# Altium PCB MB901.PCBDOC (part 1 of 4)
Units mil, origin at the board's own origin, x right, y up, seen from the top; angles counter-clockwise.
Board outline 4505 x 7005 mil, 4 copper layers (TopLayer, GND, VCC, BottomLayer); 333 components, 312 nets, 1570 pads, 794 vias.
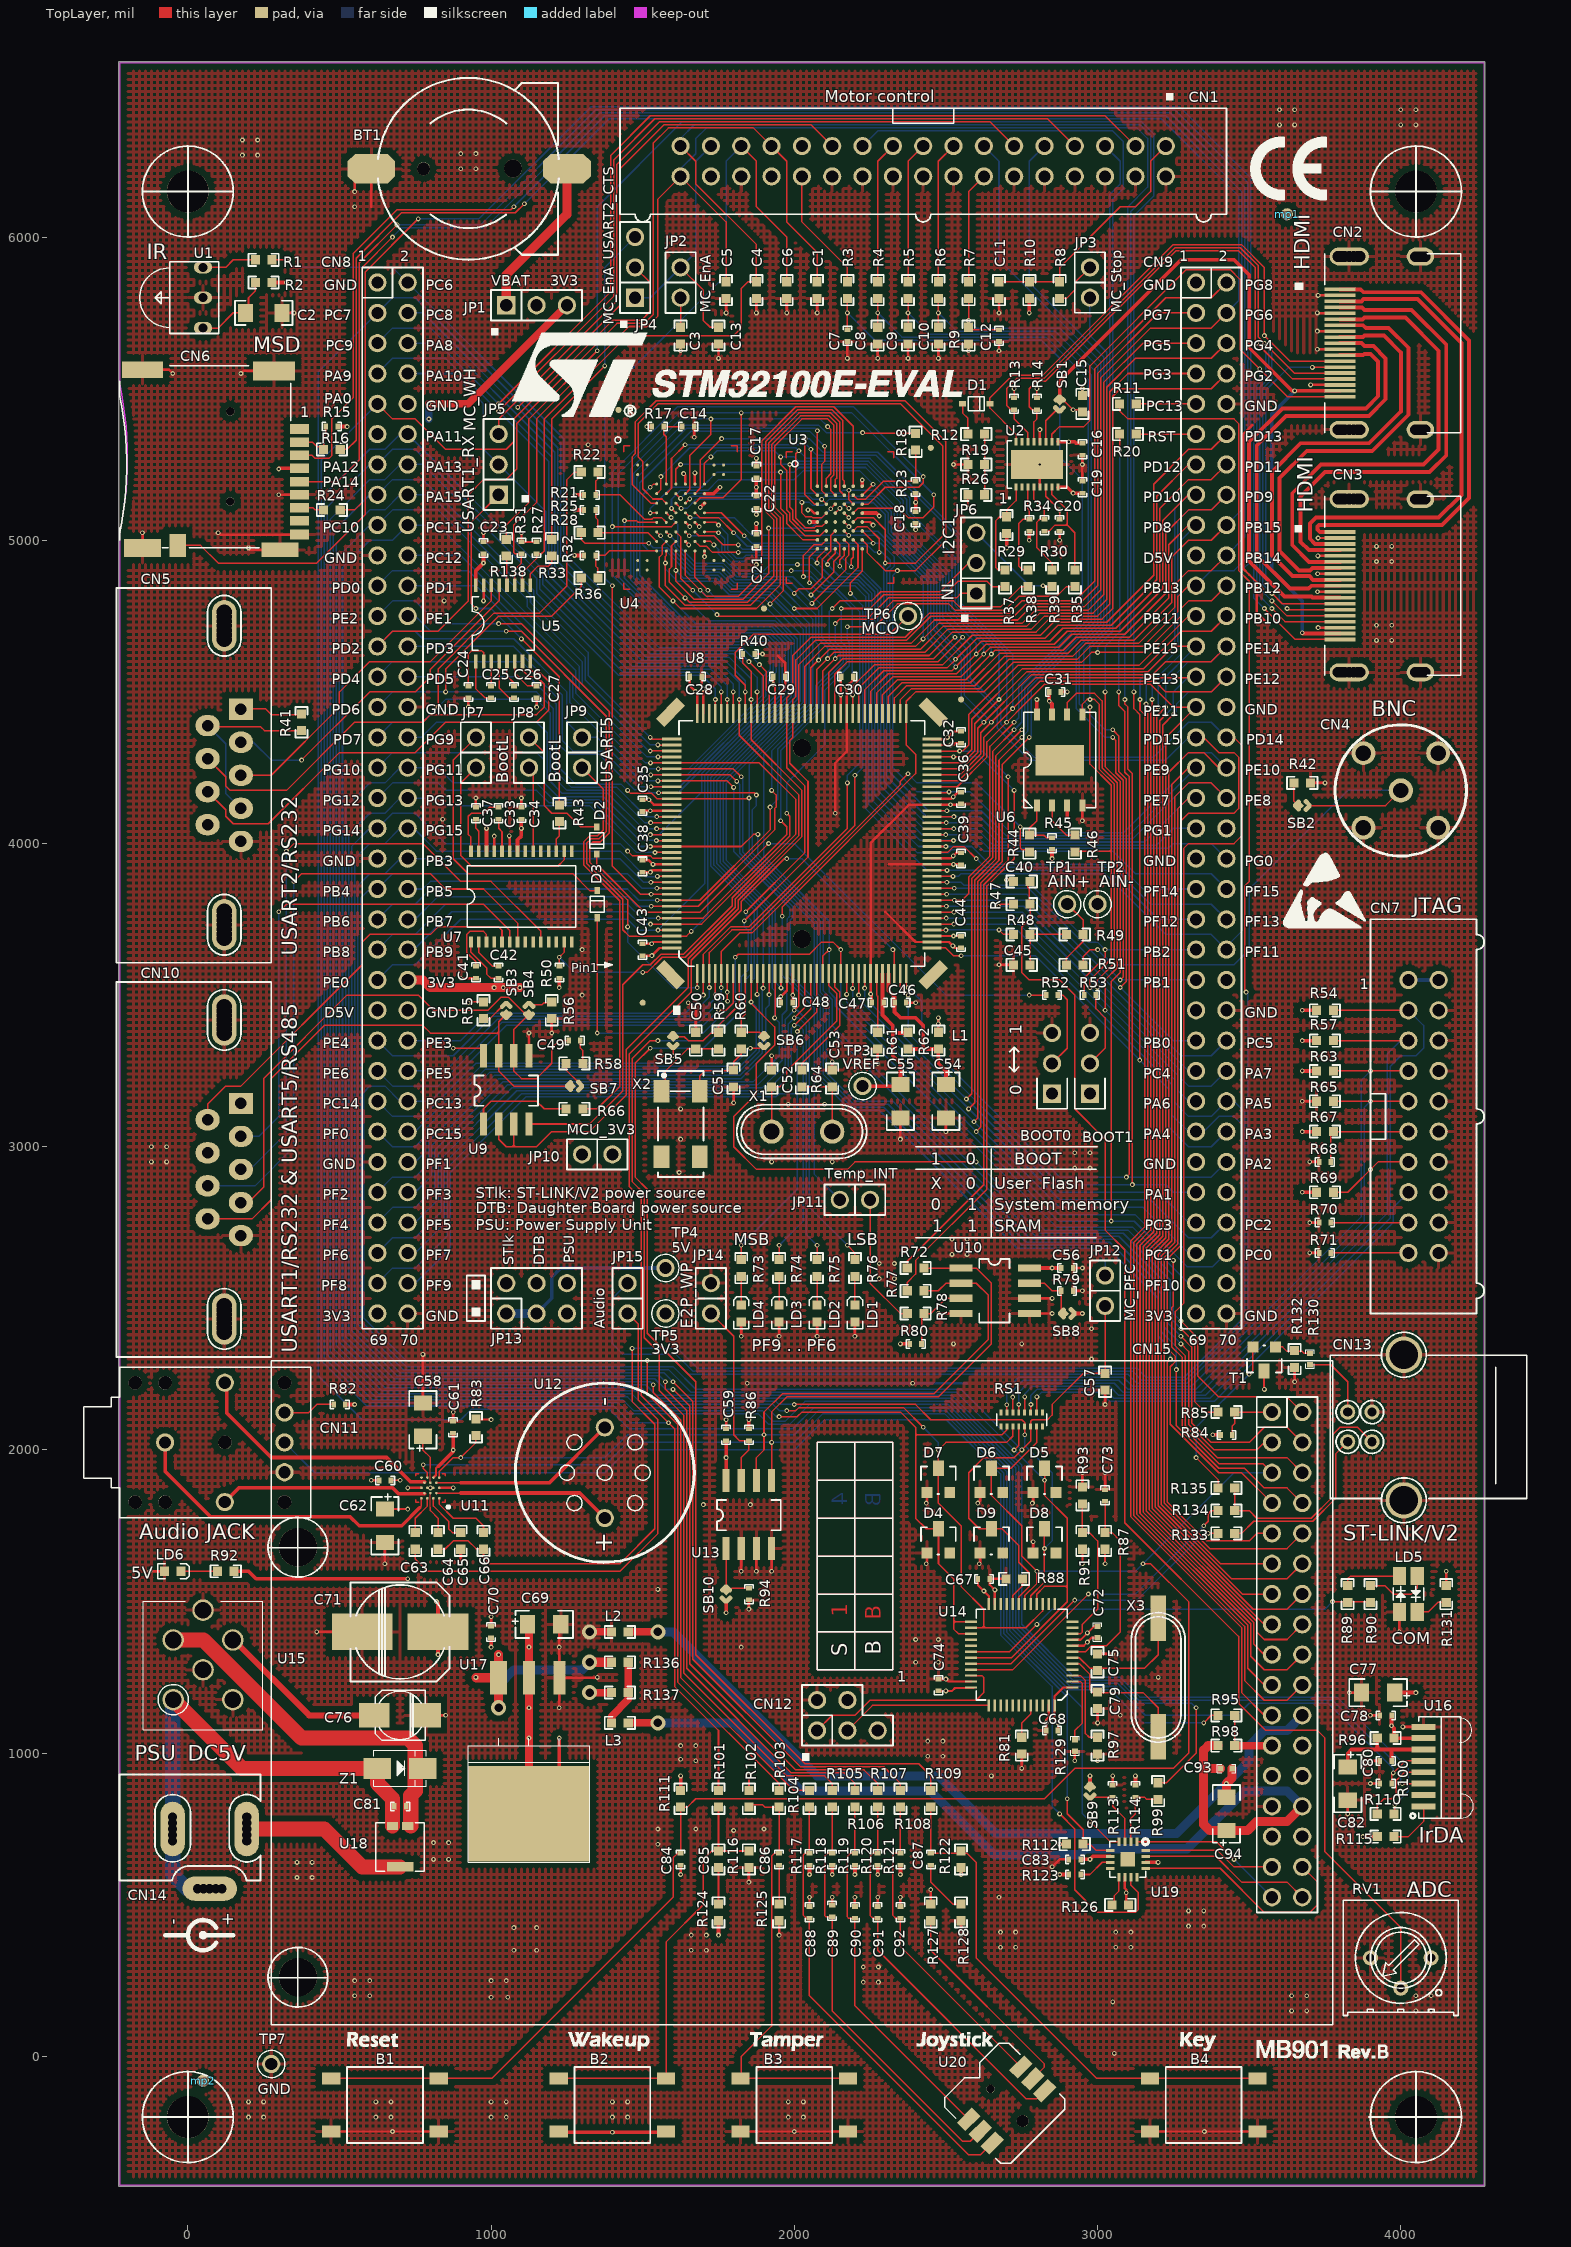
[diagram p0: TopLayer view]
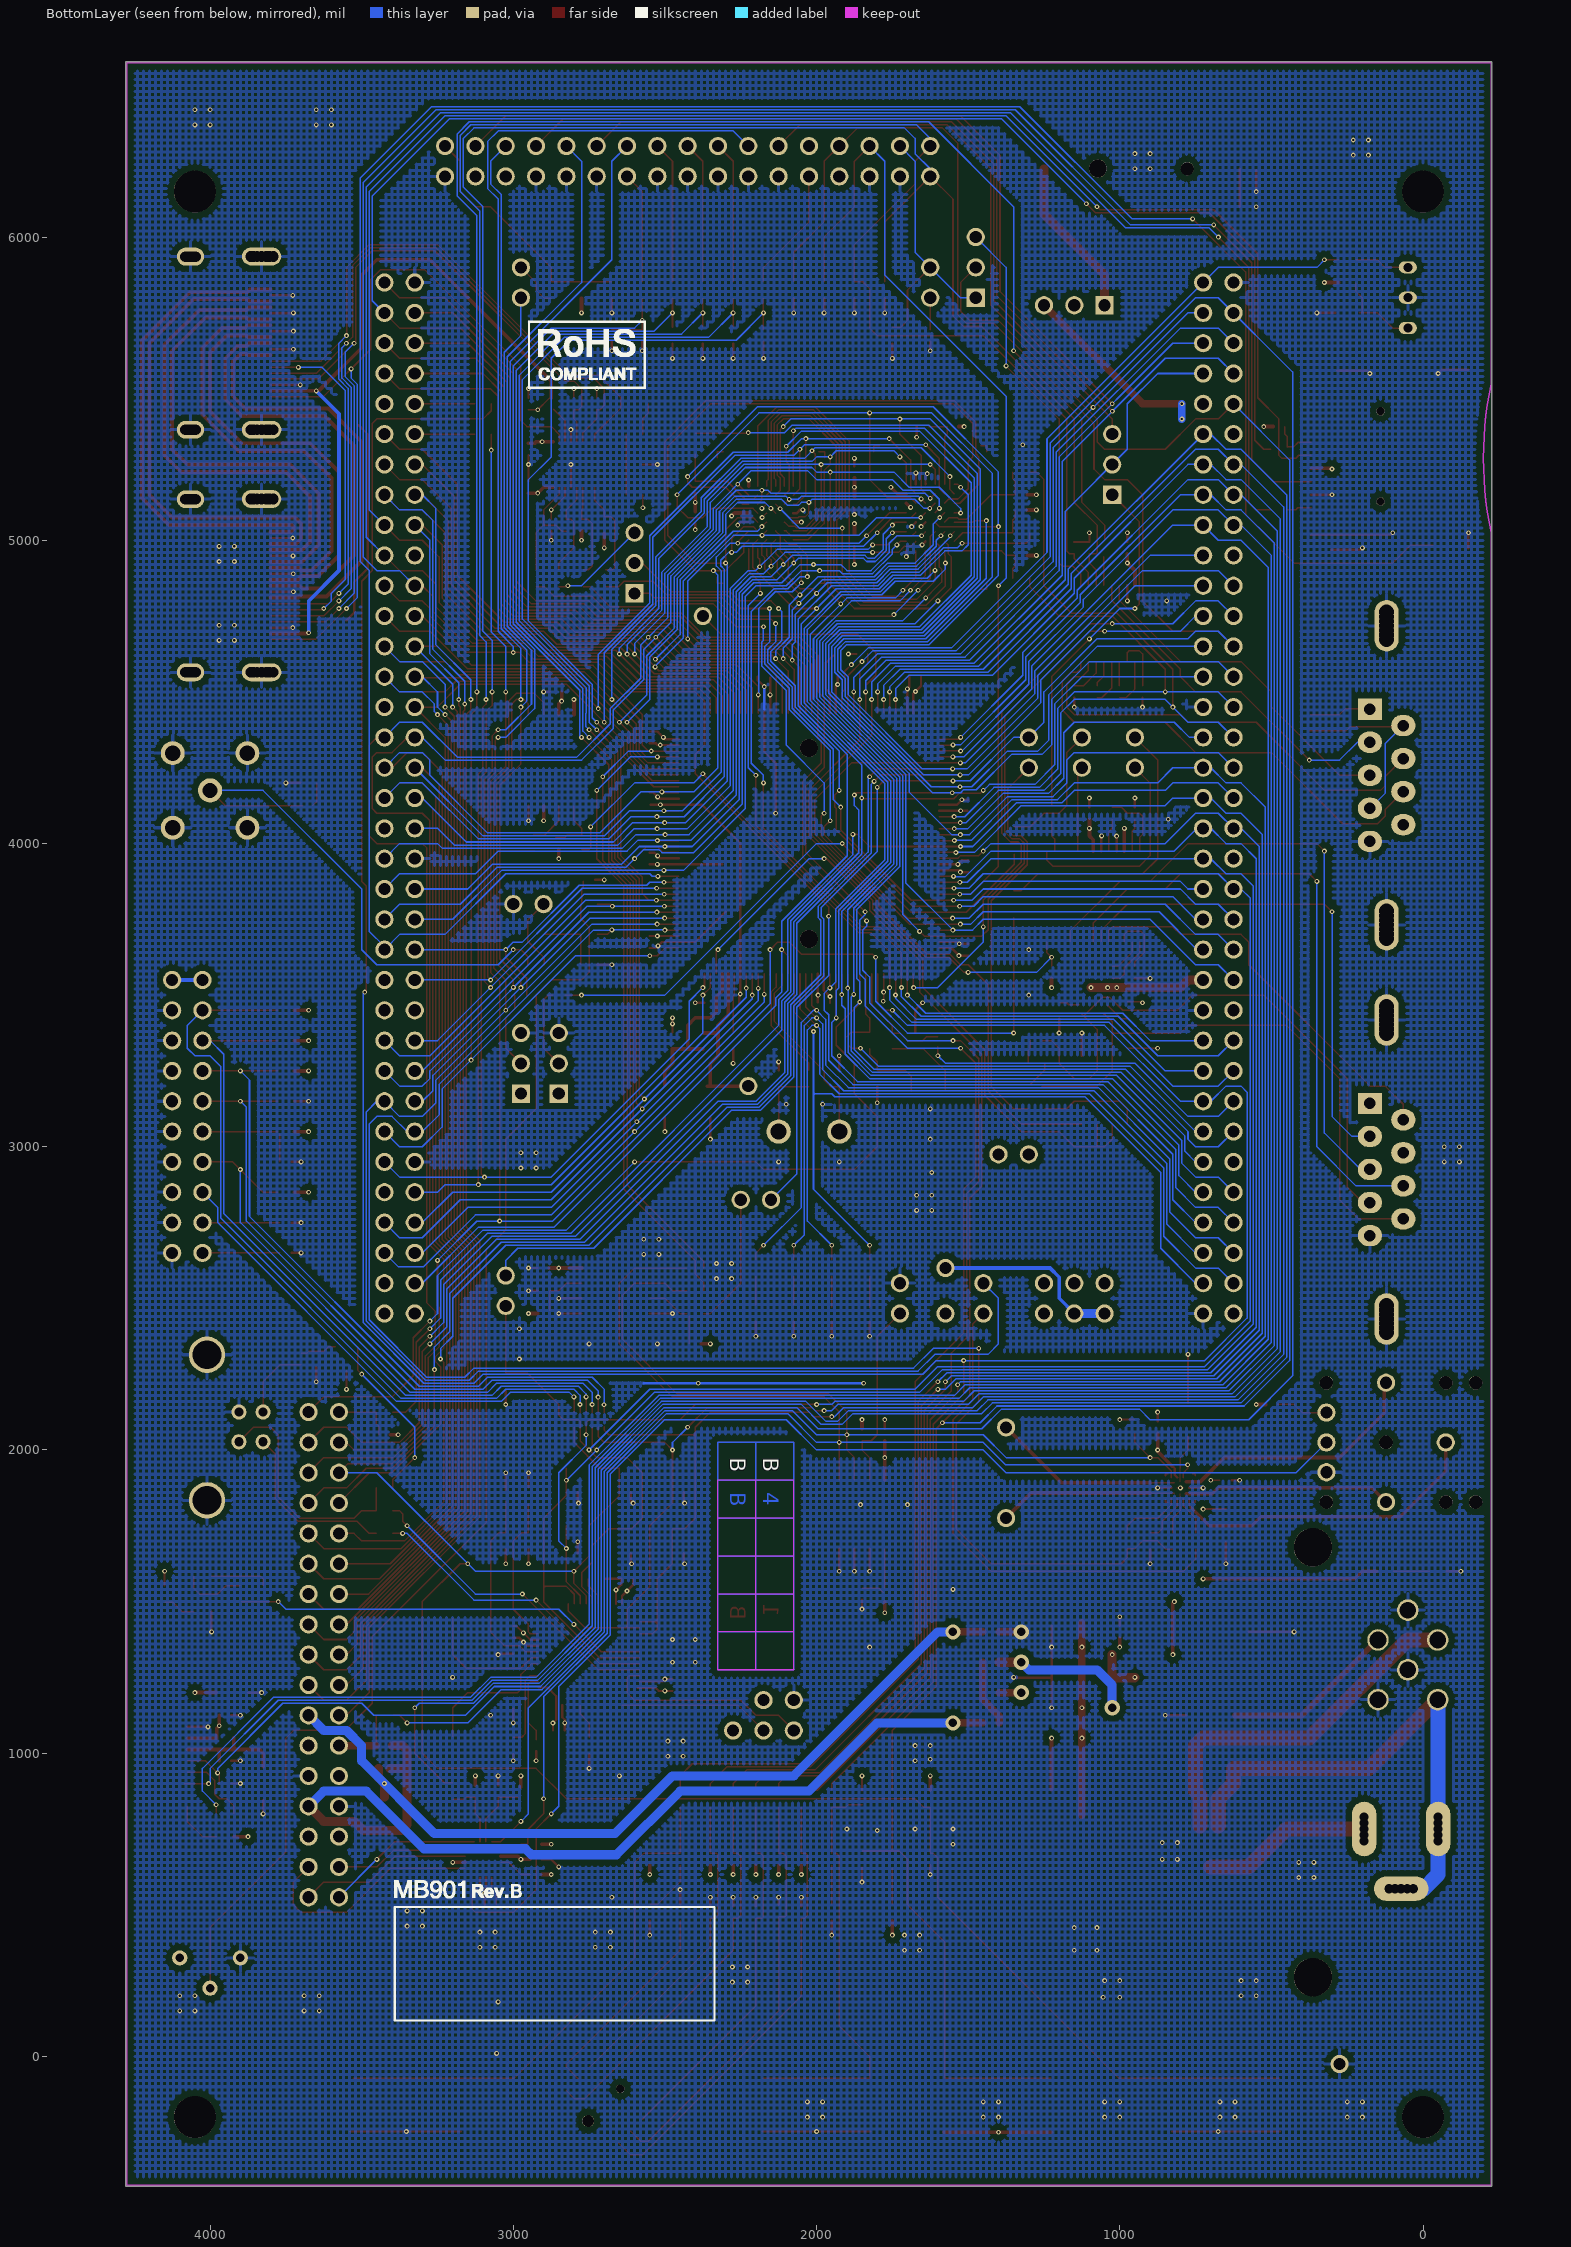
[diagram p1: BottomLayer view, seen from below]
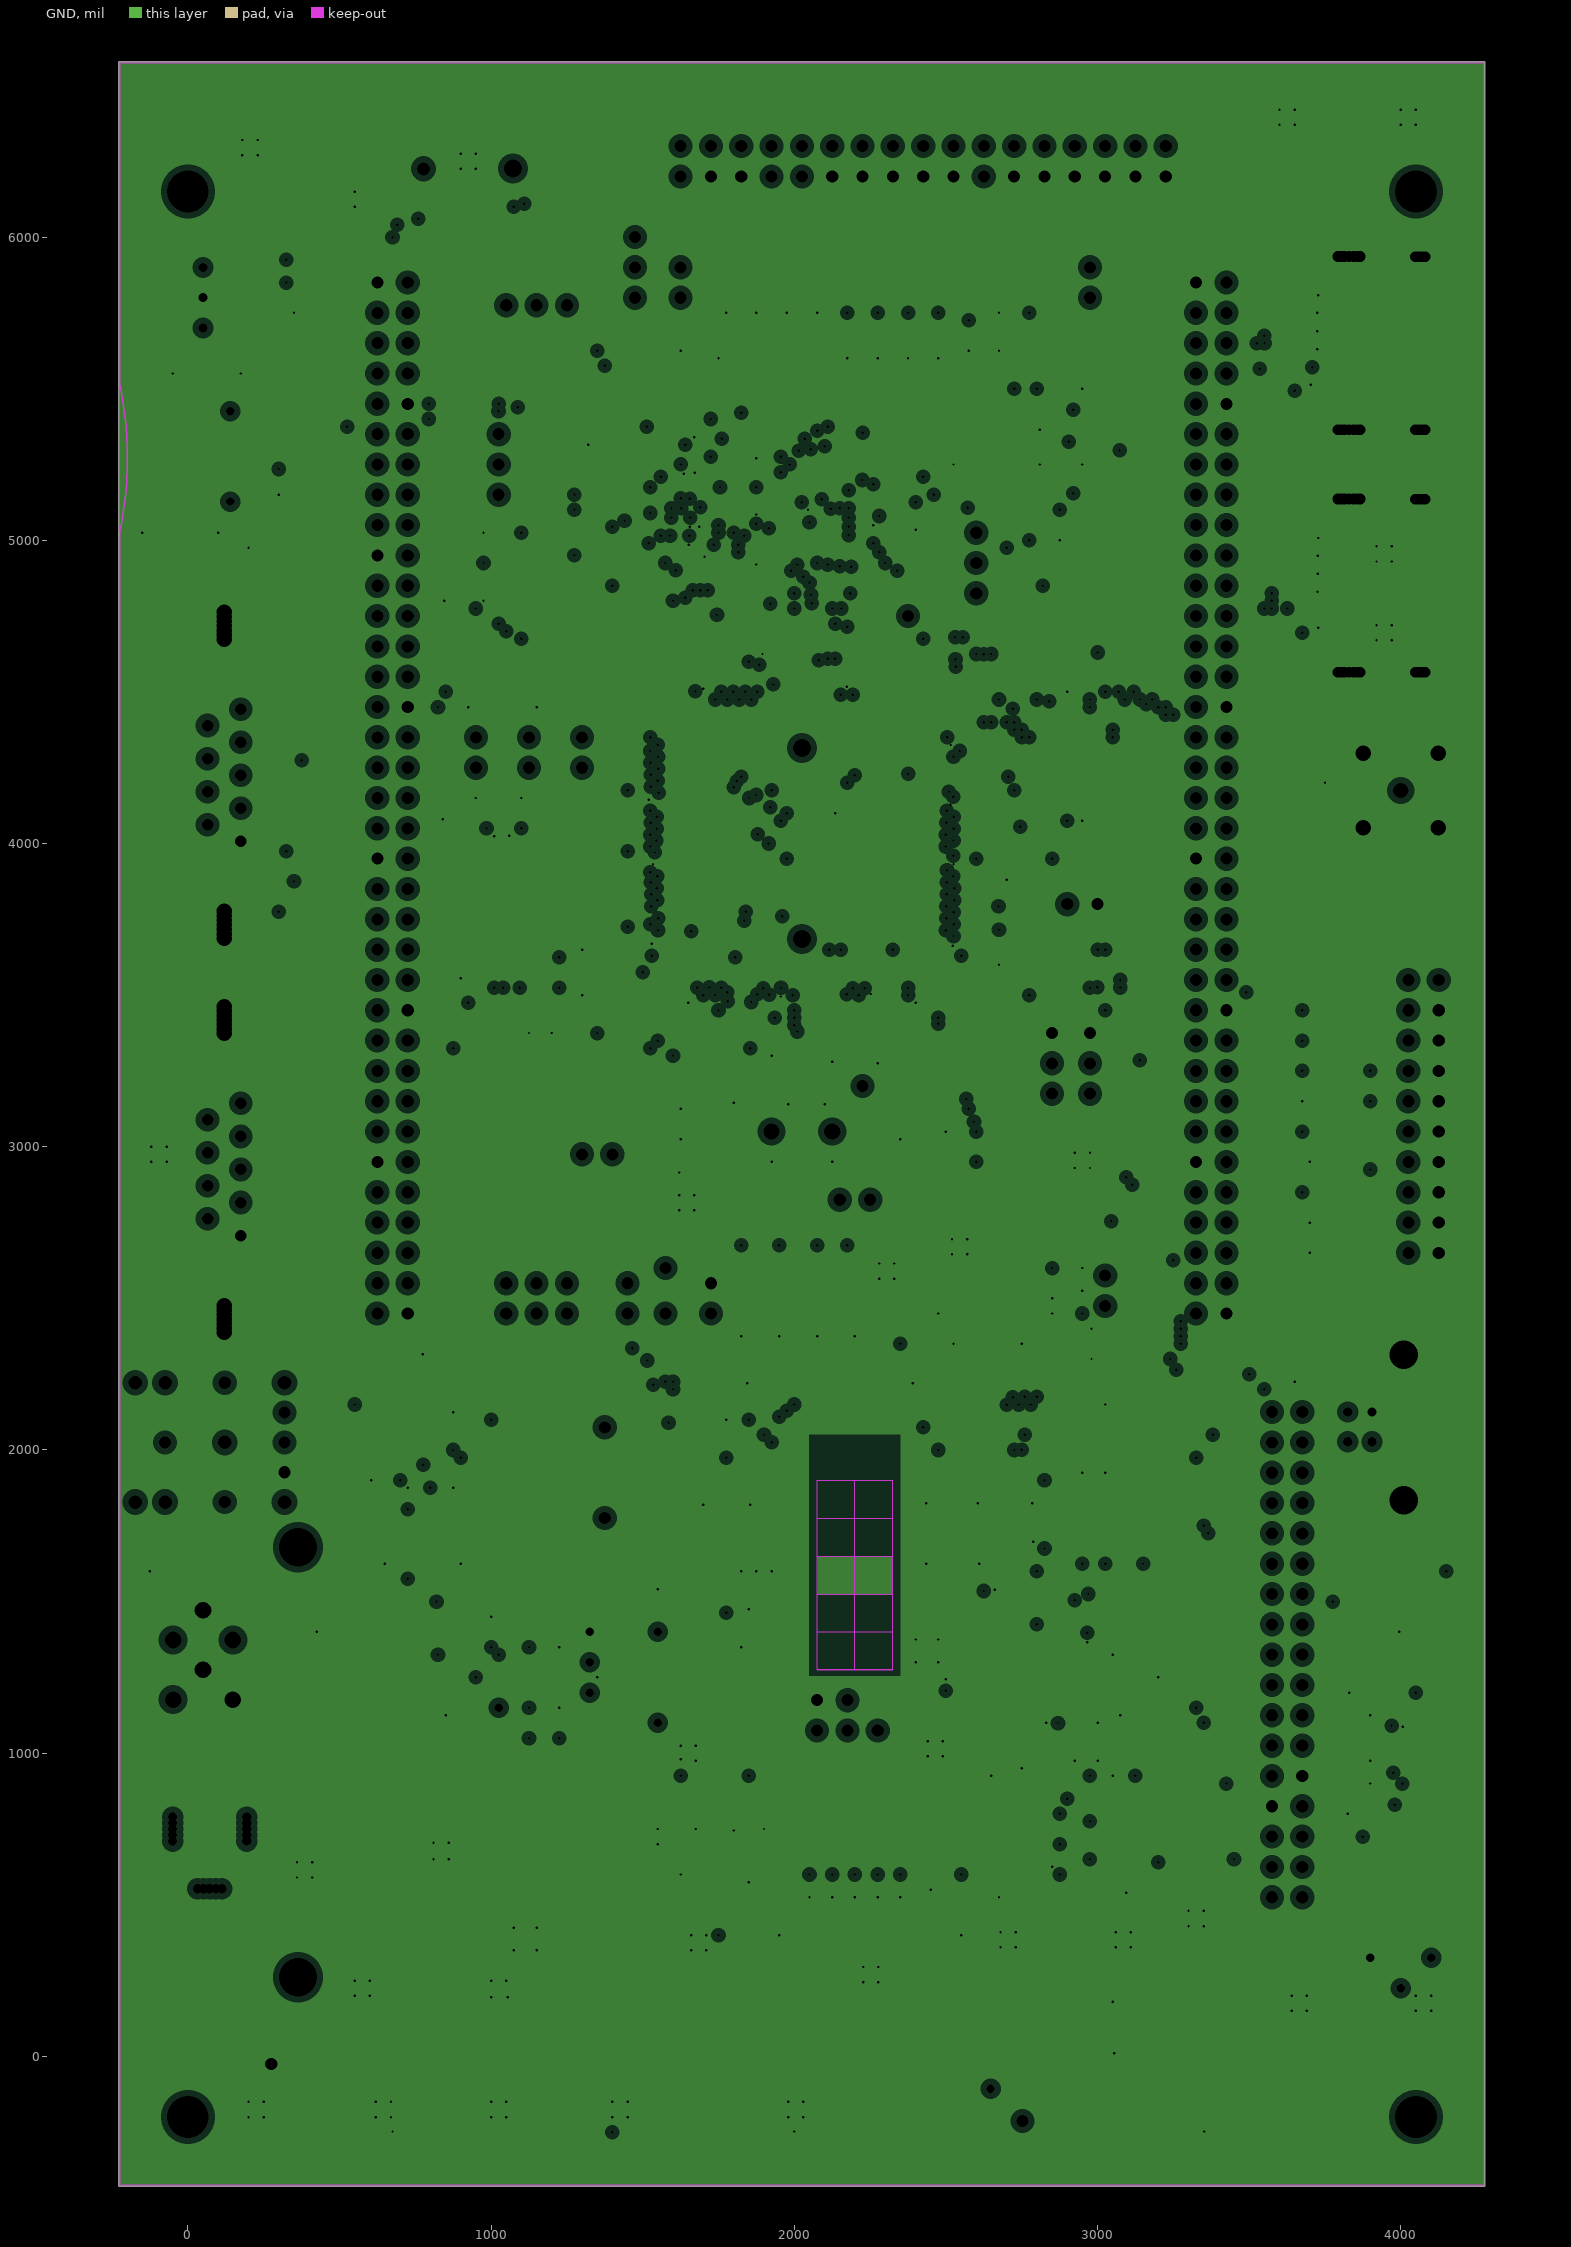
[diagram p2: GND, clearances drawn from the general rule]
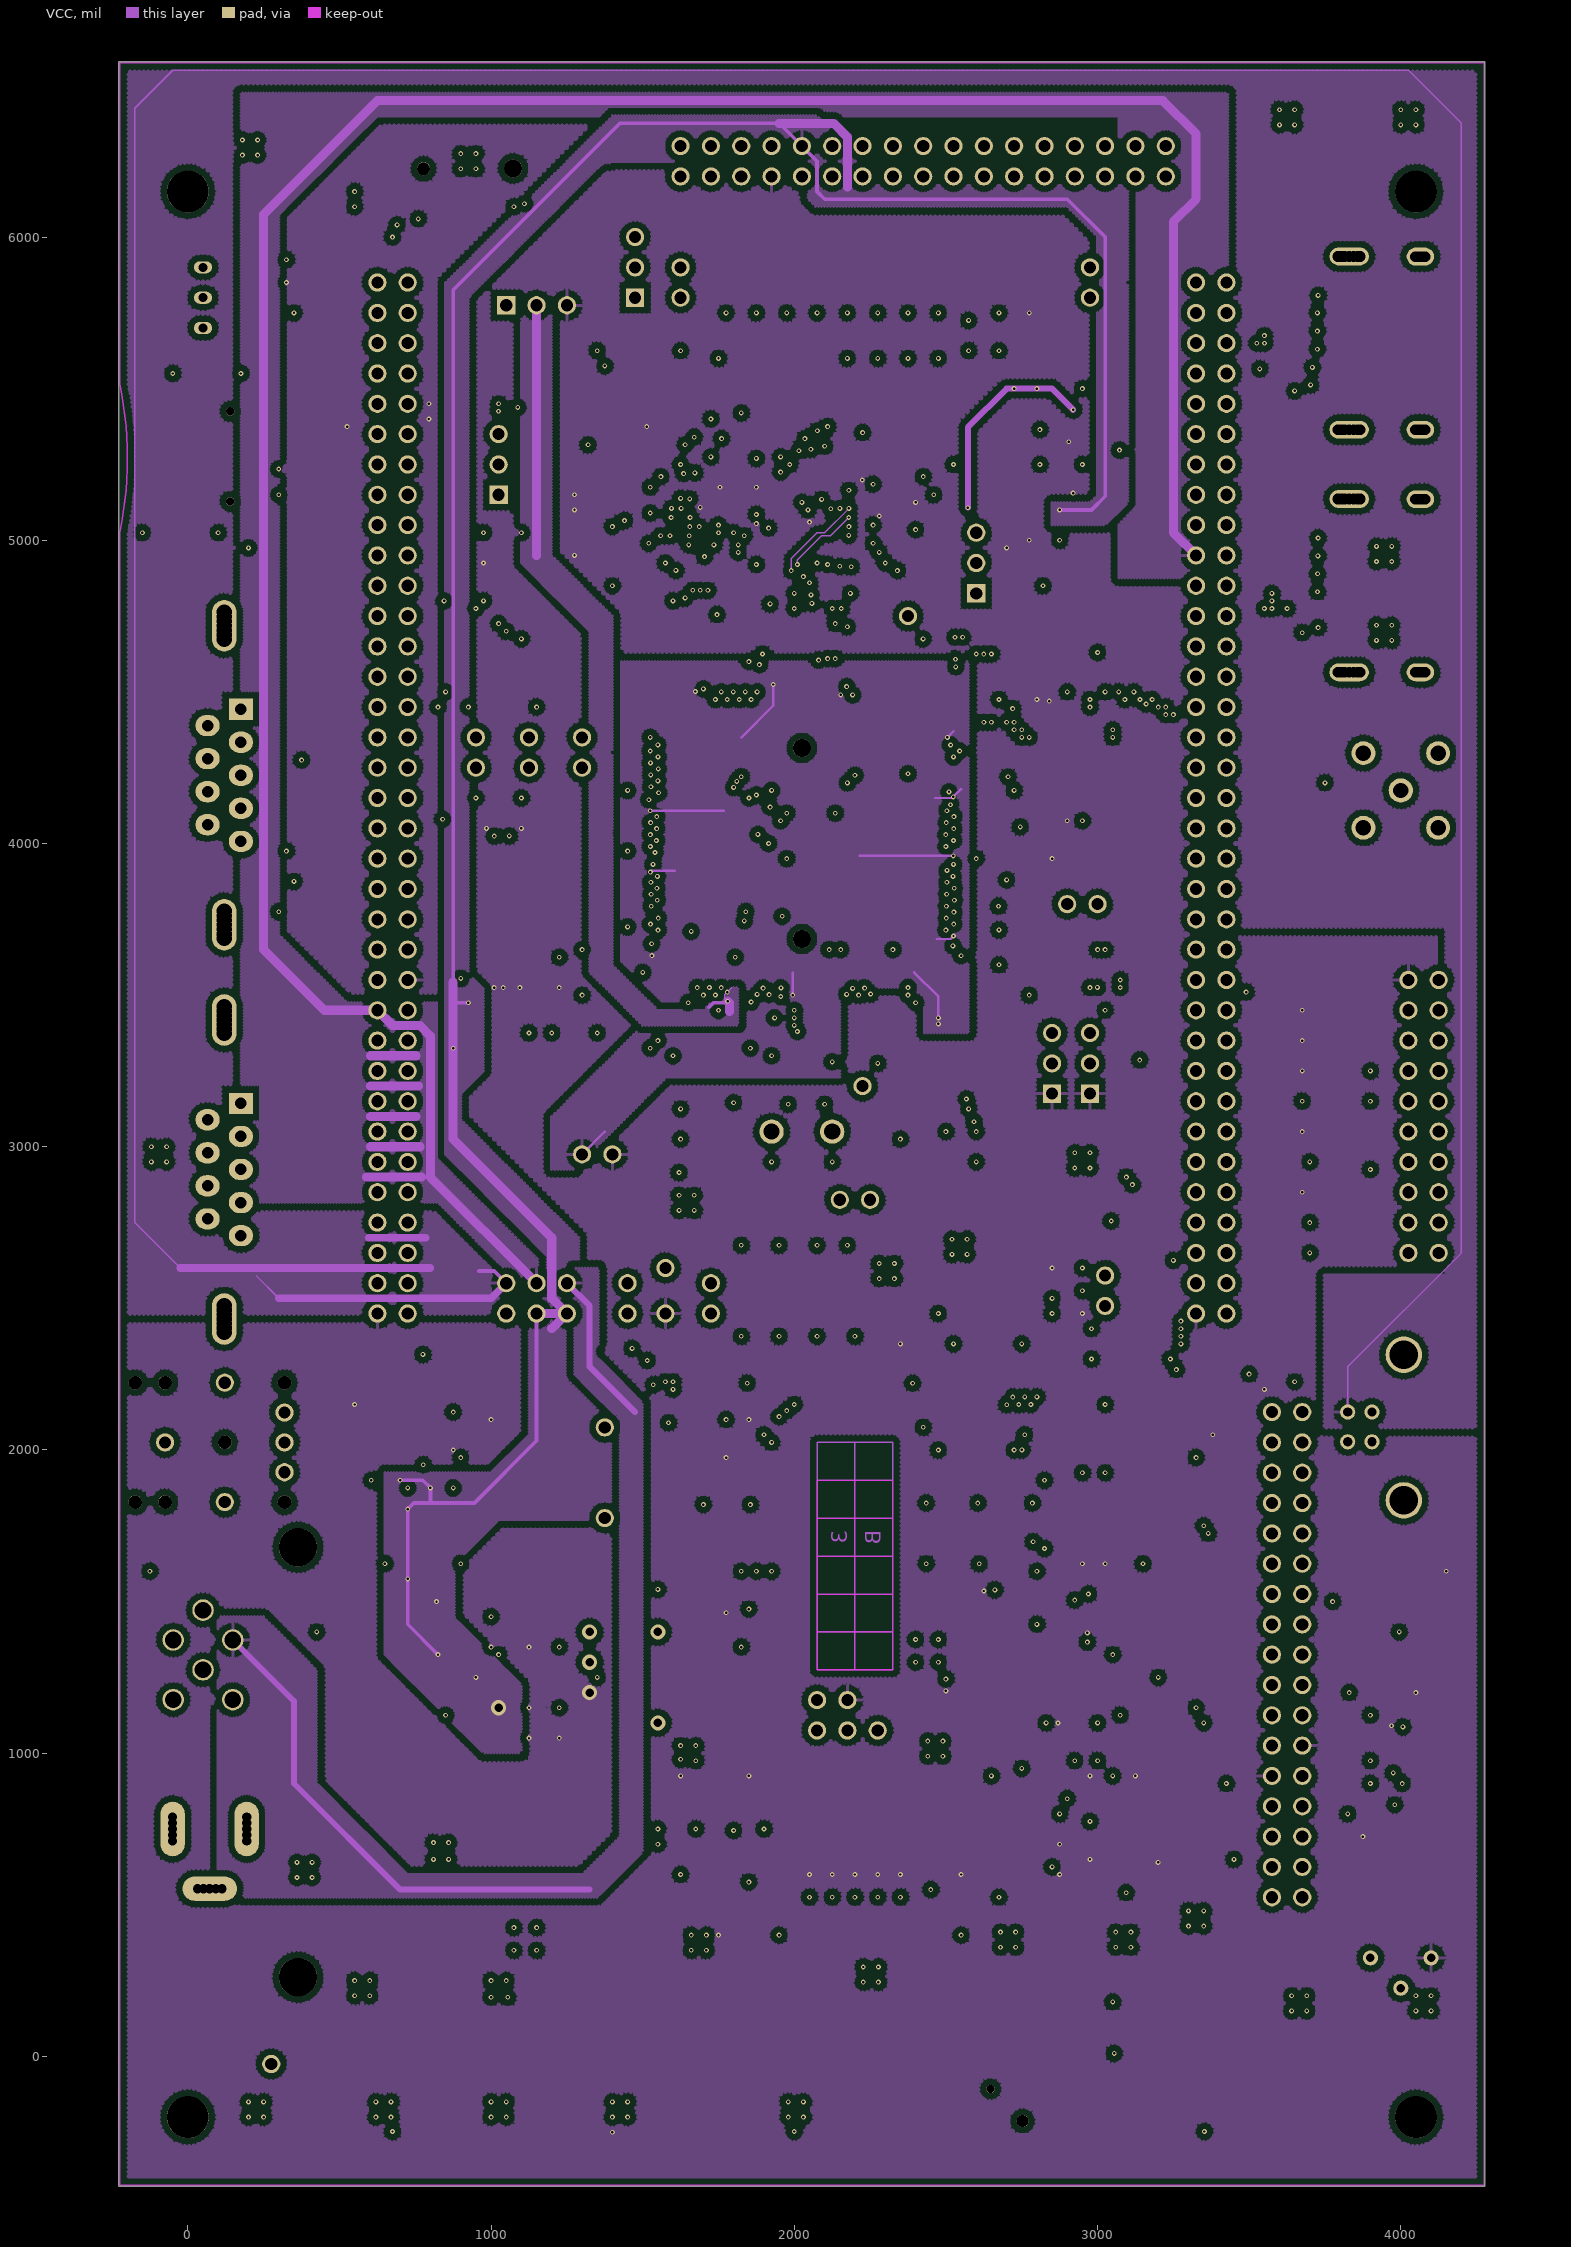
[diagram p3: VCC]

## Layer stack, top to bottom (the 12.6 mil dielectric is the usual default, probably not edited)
TopLayer: signal copper 1.4
Dielectric: core 12.6, FR-4, Dk 4.8
GND: plane copper 1.4, net GND
Dielectric: prepreg 12.6, FR-4, Dk 4.8
VCC: signal copper 1.4
Dielectric: core 12.6, FR-4, Dk 4.8
BottomLayer: signal copper 1.4

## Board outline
-227.5,-427.5 4277.5,-427.5 4277.5,6577.5 -227.5,6577.5

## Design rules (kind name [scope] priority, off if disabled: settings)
Clearance Clearance_3 [InComponent('U11')] p1: gap=4
Clearance Clearance_1 [(InPoly)] p2: gap=20 // Protel DXP Scope 1 Expression Was: (InPoly)   Protel DXP Scope 1 Expression Was: (InPoly)
Clearance [All] p3: gap=5
ComponentClearance [All] p1 off: gap=10 collisioncheckmode=0
PlaneClearance [All] p1: clearance=20
PlaneConnect [All] p1: planeconnectstyle=Relief reliefexpansion=20 reliefentries=4 reliefconductorwidth=10 reliefairgap=10
PolygonConnect [All] p1: connectstyle=Relief reliefconductorwidth=10 reliefentries=4 polygonreliefangle="90 Angle"
RoutingLayers [All] p1: top layer=Horizontal mid layer 1="Not Used" bottom layer=Vertical
RoutingVias [All] p1: holewidth=8 width=16 viastyle="Through Hole" minholewidth=5 minwidth=8 maxholewidth=28 maxwidth=50
SolderMaskExpansion [All] p1: expansion=4
TestPointUsage [All] p1: valid=0 allowmultiple=FALSE
Testpoint [All] p1: side=15 testpointundercomponent=TRUE minsize=40 maxsize=100 preferedsize=60 minholesize=20 maxholesize=40 preferedholesize=32 testpointgrid=1 style=1023 order=1234567890
Width Width_4 [InNet('E5V')] p1: maxlimit=300 minlimit=7 preferedwidth=20
Width Width_3 [InNet('D5V')] p2: maxlimit=300 minlimit=7 preferedwidth=30
Width Width_1 [InNet('+3V3')] p3: maxlimit=300 minlimit=7 preferedwidth=12
Width Width_5 [InNet('GND')] p4: maxlimit=300 minlimit=7 preferedwidth=8
Width Width_8 [InNet('VDDA')] p5: maxlimit=300 minlimit=7 preferedwidth=12
Width Width_7 [InNet('VDD')] p6: maxlimit=300 minlimit=7 preferedwidth=8
Width Width_6 [InNet('U5V')] p7: maxlimit=300 minlimit=7 preferedwidth=12
Width Width_2 [InNet('+5V')] p8: maxlimit=300 minlimit=5 preferedwidth=12
Width [All] p9: maxlimit=300 minlimit=5 preferedwidth=5
14 further rules are at their usual default settings.

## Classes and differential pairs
net class A[0..20]: A0 A1 A2 A3 A4 A5 A6 A7 A8 A9 A10 A11 A12 A13 A14 A15 A16 A17 A18 A19 A20 A[0..20]0 A[0..20]1 A[0..20]2 A[0..20]3 A[0..20]4 A[0..20]5 A[0..20]6 A[0..20]7 A[0..20]8 A[0..20]9 A[0..20]10 A[0..20]11 A[0..20]12 A[0..20]13 A[0..20]14 A[0..20]15 A[0..20]16 A[0..20]17 A[0..20]18 A[0..20]19 A[0..20]20
component class MB901: R72 R77 R83 R112
component class SRAM&OneNAND: C14 C17 C18 C21 C22 R17 R18 R21 R22 R23 R25 R28 R32 R36 U3 U4
component class MicroSD&SPIFlash: C31 CN6 R15 R16 R24 R44 R45 R46 U6
component class LCD&EEPROM&TS: C56 C59 C83 CN15 JP14 R78 R79 R80 R84 R85 R86 R94 R95 R98 R99 R113 R114 R123 R126 SB8 SB9 SB10 U10 U13 U19
component class ST_LINK: C67 C68 C72 C73 C74 C75 C79 CN12 CN13 LD5 R81 R87 R88 R89 R90 R91 R93 R97 U14 X3
component class CEC&IRreceiver: C2 C15 C16 C19 C20 CN2 CN3 D1 R1 R2 R12 R13 R14 R19 R26 R29 R30 R34 R35 R37 R38 R39 SB1 U1 U2
component class IO_Peripheral: B2 B3 B4 C40 C45 C85 C86 C87 C88 C89 C90 C91 C92 CN4 LD3 LD4 R42 R47 R48 R49 R51 R73 R74 R75 R76 R101 R102 R103 R104 R105 R106 R107 R108 R109 R116 R117 R118 R119 R120 R121 R122 R124 R125 R127 R128 RV1 SB2 TP1 TP2 U20
net class A[0..23]: A0 A1 A2 A3 A4 A5 A6 A7 A8 A9 A10 A11 A12 A13 A14 A15 A16 A17 A18 A19 A20 A21 A22 A23 A[0..23]0 A[0..23]1 A[0..23]2 A[0..23]3 A[0..23]4 A[0..23]5 A[0..23]6 A[0..23]7 A[0..23]8 A[0..23]9 A[0..23]10 A[0..23]11 A[0..23]12 A[0..23]13 A[0..23]14 A[0..23]15 A[0..23]16 A[0..23]17 A[0..23]18 A[0..23]19 A[0..23]20 A[0..23]21 A[0..23]22 A[0..23]23
net class D[0..15]: D0 D1 D2 D3 D4 D5 D6 D7 D8 D9 D10 D11 D12 D13 D14 D15 D[0..15]0 D[0..15]1 D[0..15]2 D[0..15]3 D[0..15]4 D[0..15]5 D[0..15]6 D[0..15]7 D[0..15]8 D[0..15]9 D[0..15]10 D[0..15]11 D[0..15]12 D[0..15]13 D[0..15]14 D[0..15]15
net class A[0..25]: A0 A1 A2 A3 A4 A5 A6 A7 A8 A9 A10 A11 A12 A13 A14 A15 A16 A17 A18 A21 A22 A[0..25]0 A[0..25]1 A[0..25]2 A[0..25]3 A[0..25]4 A[0..25]5 A[0..25]6 A[0..25]7 A[0..25]8 A[0..25]9 A[0..25]10 A[0..25]11 A[0..25]12 A[0..25]13 A[0..25]14 A[0..25]15 A[0..25]16 A[0..25]17 A[0..25]18 A[0..25]19 A[0..25]20 A[0..25]21 A[0..25]22 A[0..25]23 A[0..25]24 A[0..25]25 D0 D1 PD3 PG13 PG14
component class MotorCtrl_2: C28 C29 C30 C32 C35 C36 C39 C43 C44 C48 CN8 JP26 R36 R49 R51 R61 R62 R72 R96 R113
component class SRAM&Flash: C24 C25 C27 C40 C50 C53 C73 C84 JP2 JP5 JP7 JP9 R2 R12 R26 R28 R31 R35 R68 U11 U12
component class CFcard: C27 C50 C53 CN4 R12 R25 R28 R31 R35 R44 R46 R52 R67 R71 U11
net class PE[0..15]: A19 A20 A21 A22 A23 NetR41_2 NetR115_2 PE7 PE8 PE9 PE10 PE11 PE12 PE13 PE14 PE15 PE[0..15]0 PE[0..15]1 PE[0..15]2 PE[0..15]3 PE[0..15]4 PE[0..15]5 PE[0..15]6 PE[0..15]7 PE[0..15]8 PE[0..15]9 PE[0..15]10 PE[0..15]11 PE[0..15]12 PE[0..15]13 PE[0..15]14 PE[0..15]15
net class PD[0..15]: NetR72_2 NetR96_2 NetU14_4 NetU14_5 PB14 PD0 PD1 PD2 PD3 PD4 PD5 PD6 PD10 PD11 PD13 PD[0..15]0 PD[0..15]1 PD[0..15]2 PD[0..15]3 PD[0..15]4 PD[0..15]5 PD[0..15]6 PD[0..15]7 PD[0..15]8 PD[0..15]9 PD[0..15]10 PD[0..15]11 PD[0..15]12 PD[0..15]13 PD[0..15]14 PD[0..15]15 PG7
net class PC[0..15]: NetC50_1 PC0 PC1 PC2 PC3 PC4 PC5 PC6 PC7 PC8 PC9 PC10 PC11 PC12 PC13 PC15 PC[0..15]0 PC[0..15]1 PC[0..15]2 PC[0..15]3 PC[0..15]4 PC[0..15]5 PC[0..15]6 PC[0..15]7 PC[0..15]8 PC[0..15]9 PC[0..15]10 PC[0..15]11 PC[0..15]12 PC[0..15]13 PC[0..15]14 PC[0..15]15
net class PB[0..15]: NetR78_1 NetU15_5 PB0 PB1 PB2 PB3 PB4 PB8 PB10 PB11 PB12 PB13 PB14 PB[0..15]0 PB[0..15]1 PB[0..15]2 PB[0..15]3 PB[0..15]4 PB[0..15]5 PB[0..15]6 PB[0..15]7 PB[0..15]8 PB[0..15]9 PB[0..15]10 PB[0..15]11 PB[0..15]12 PB[0..15]13 PB[0..15]14 PB[0..15]15 PG8 TEMPERATURESENSOR_SCL TEMPERATURESENSOR_SDA
net class PA[0..15]: PA0 PA1 PA2 PA3 PA4 PA5 PA6 PA7 PA8 PA9 PA10 PA11 PA12 PA13 PA14 PA15 PA[0..15]0 PA[0..15]1 PA[0..15]2 PA[0..15]3 PA[0..15]4 PA[0..15]5 PA[0..15]6 PA[0..15]7 PA[0..15]8 PA[0..15]9 PA[0..15]10 PA[0..15]11 PA[0..15]12 PA[0..15]13 PA[0..15]14 PA[0..15]15
component class Extension: CN1 CN14 R103 R109
component class JTAG&SWD: CN1 CN5 CN18 JP19 R4 R5 R6 R7 R8 R9 R10 R27 R31 R55 R64 R92 R100
component class MotorCtrl: C1 C6 C23 C24 C33 C57 C71 C86 C87 C90 C91 C92 CN5 JP5 JP12 R14 R61 R76 R82 R88 R91 R105 R107
component class MCU: B1 BOOT0 BOOT1 BT1 C4 C5 C6 C8 C9 C13 C23 C37 C57 C67 C75 C77 JP7 L1 R12 R48 R90 R119 R120 R121 R125 R128 TP10 U8 X1 X2
component class Peripherals: C7 C31 C39 C68 C79 CN3 CN4 CN9 JP8 JP9 JP14 LD3 LD4 LD6 R3 R11 R14 R19 R25 R27 R30 R44 R46 R47 R52 R56 R61 R63 R67 R69 R71 R75 R76 R82 R83 R101 R102 R103 R105 R107 R109 R110 R111 R125 RV1 T1 T2 TR1 TR2 U2 U4 U6 U15
component class Power: C69 C70 C71 C76 C81 CN14 JP13 LD4 R92 TP4 TP5 TP7 U15 U17 U18 Z1
component class RS232&IrDA: C23 C24 C25 C26 C27 C32 C38 C47 C48 C77 C78 C80 C81 C82 CN5 CN10 JP15 R33 R41 R50 R57 R83 R96 R100 R110 R115 U5 U16 U18
component class Audio: C25 C27 C40 C50 C53 C73 C84 C85 CN7 JP11 JP16 R2 R12 R25 R26 R28 R35 R44 R46 R52 R55 R67 R68 R71 R105 RV2 RV3 TP4 TP5 TP7 TP15 U15 U18 U19 U20
component class LCD&Joystick: B1 B2 B4 C33 C85 C86 C87 C88 C89 C90 C91 C92 R5 R10 R58 R87 R101 R102 R103 R104 R105 R106 R107 R108 R109 R115 R116 R117 R118 R119 R120 R121 R122 R124 R125 R127 R128 U18 U19 U20
component class MC&Extension: C1 C6 C23 C24 C33 C71 C86 C87 C90 C91 C92 CN1 CN5 CN14 JP12 R14 R61 R76 R82 R88 R91 R103 R105 R109
component class SD&SmartCard: C1 C6 C57 C69 C76 C81 CN1 CN10 R4 R31 R41 R50 R96 R100 R101 R115 R116 R117 R119 TP8 TP9 U15
component class Debug: CN1 CN5 CN9 CN18 JP19 R4 R5 R8 R9 R10 R27 R64 R92

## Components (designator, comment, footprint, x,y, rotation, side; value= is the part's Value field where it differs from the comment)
B1 "RESET" PB10 650,-160 r90 top
B2 "WKUP" PB10 1400,-160 r90 top
B3 "Tamper" PB10 2000,-160 r90 top
B4 "USER" PB10 3350,-160 r90 top
BOOT0 "" SIP3 2850,3175 r90 top
BOOT1 "" SIP3 2975,3175 r90 top
BT1 "CR1220 holder" LI1220_1 925,6225 r0 top
C1 "[N/A]" 0603C 2075,5825 r270 top
C2 "4.7uF" 1206C 250,5750 r180 top
C3 "10nF" 0603C 1625,5675 r270 top
C4 "[N/A]" 0603C 1875,5825 r270 top
C5 "[N/A]" 0603C 1775,5825 r270 top
C6 "[N/A]" 0603C 1975,5825 r270 top
C7 "100nF" 0402C#1 2175,5675 r270 top
C8 "[N/A]" 0603C 2275,5675 r270 top
C9 "[N/A]" 0603C 2375,5675 r270 top
C10 "[N/A]" 0603C 2475,5675 r270 top
C11 "1nF" 0603C 2675,5825 r270 top
C12 "100nF" 0402C#1 2675,5675 r270 top
C13 "[N/A]" 0603C 1750,5675 r270 top
C14 "100nF" 0402C#1 1650,5375 r0 top
C15 "10nF" 0603C 2950,5450 r270 top
C16 "100nF" 0402C#1 2950,5300 r90 top
C17 "100nF" 0402C#1 1875,5225 r90 top
C18 "100nF" 0402C#1 2400,5075 r90 top
C19 "100nF" 0402C#1 2950,5175 r270 top
C20 "100nF" 0402C#1 2875,5050 r90 top
C21 "100nF" 0402C#1 1875,5000 r90 top
C22 "100nF" 0402C#1 1875,5125 r270 top
C23 "100nF" 0402C#1 975,4975 r270 top
C24 "100nF" 0402C#1 925,4500 r270 top
C25 "100nF" 0402C#1 1000,4500 r270 top
C26 "100nF" 0402C#1 1075,4500 r270 top
C27 "100nF" 0402C#1 1150,4500 r270 top
C28 "100nF" 0402C#1 1675,4550 r180 top
C29 "100nF" 0402C#1 1950,4550 r180 top
C30 "100nF" 0402C#1 2175,4550 r180 top
C31 "100nF" 0402C#1 2860,4500 r0 top
C32 "100nF" 0402C#1 2550,4350 r90 top
C33 "100nF" 0402C#1 1025,4100 r270 top
C34 "100nF" 0402C#1 1100,4100 r90 top
C35 "100nF" 0402C#1 1500,4125 r270 top
C36 "100nF" 0402C#1 2550,4150 r90 top
C37 "100nF" 0402C#1 950,4100 r270 top
C38 "100nF" 0402C#1 1500,3925 r270 top
C39 "100nF" 0402C#1 2550,3950 r90 top
C40 "10nF" 0603C 2750,3875 r180 top
C41 "100nF" 0402C#1 950,3575 r90 top
C42 "100nF" 0402C#1 1025,3575 r270 top
C43 "100nF" 0402C#1 1500,3650 r270 top
C44 "100nF" 0402C#1 2550,3675 r90 top
C45 "[N/A]" 0603C 2750,3600 r180 top
C46 "100nF" 0402C#1 2350,3475 r0 top
C47 "100nF" 0402C#1 2275,3475 r0 top
C48 "100nF" 0402C#1 1975,3475 r0 top
C49 "100nF" 0402C#1 1275,3350 r0 top
C50 "6.8pF" 0603C 1675,3350 r270 top
C51 "6.8pF" 0603C 1800,3225 r90 top
C52 "20pF" 0603C 1925,3225 r270 top
C53 "20pF" 0603C 2125,3225 r270 top
C54 "1uF" TAN-A#1 2500,3150 r270 top
C55 "1uF" TAN-A#1 2350,3150 r270 top
C56 "100nF" 0402C#1 2900,2600 r0 top
C57 "[N/A]" 0603C 3025,2225 r270 top
C58 "1uF" TAN-A#1 775,2100 r90 top
C59 "100nF" 0402C#1 1775,2050 r90 top
C60 "100nF" 0402C#1 650,1900 r0 top
C61 "100nF" 0402C#1 875,2075 r270 top
C62 "1uF" TAN-A#1 650,1750 r270 top
C63 "330nF" 0603C 750,1700 r90 top
C64 "330nF" 0603C 825,1700 r90 top
C65 "330nF" 0603C 900,1700 r90 top
C66 "330nF" 0603C 975,1700 r90 top
C67 "100nF" 0402C#1 2625,1575 r0 top
C68 "100nF" 0402C#1 2850,1075 r180 top
C69 "10uF" TAN-A#1 1175,1425 r0 top
C70 "100nF" 0402C#1 1000,1400 r270 top
C71 "220uF" C310M 700,1400 r0 top
C72 "100nF" 0402C#2 3000,1400 r270 top
C73 "100nF" 0402C#1 3025,1850 r90 top
C74 "100nF" 0402C#1 2475,1225 r270 top
C75 "20pF" 0603C 3000,1300 r90 top
C76 "10uF" C160M 700,1125 r180 top
C77 "4.7uF" TAN-A#1 3925,1200 r180 top
C78 "104P" 0402C#1 3950,1125 r0 top
C79 "20pF" 0603C 3000,1175 r270 top
C80 "104P" 0402C#1 3950,975 r0 top
C81 "100nF" 0402C#1 700,825 r0 top
C82 "4.7uF" TAN-A#1 3825,900 r270 top
C83 "100nF" 0402C#1 2925,650 r0 top
C84 "100nF" 0402C#1 1625,650 r270 top
C85 "[N/A]" 0603C 1750,650 r270 top
C86 "100nF" 0402C#1 1950,650 r270 top
C87 "100nF" 0402C#1 2450,650 r270 top
C88 "100nF" 0402C#1 2050,475 r90 top
C89 "100nF" 0402C#1 2125,480 r90 top
C90 "100nF" 0402C#1 2200,475 r90 top
C91 "100nF" 0402C#1 2275,475 r90 top
C92 "100nF" 0402C#1 2350,475 r90 top
C93 "100nF" 0402C#2 3425,950 r180 top
C94 "10uF" TAN-A#2 3425,800 r270 top
CN1 "MC_connector" IDC34S 3225,6300 r270 top locked
CN2 "47151-0051" 0471510101 3800,5650 r90 top
CN3 "0471510101" 0471510101 3800,4850 r90 top
CN4 "VB334" VB334 4000,4175 r270 top
CN5 "DB9-male USART2" DB9/M 175,4225 r90 top
CN6 "PJS008-2000 (SMS064FF or SMS128FF)" MSD(PJS008) 140,5425 r270 top
CN7 "2316S-20G" IDC20S 4025,3550 r0 top locked
CN8 "Header 35X2" 2*35P 625,5850 r0 top locked
CN9 "Header 35X2" 2*35P 3325,5850 r0 top locked
CN10 "DB9-male USART1" DB9/M 175,2925 r90 top
CN11 "ST-212-02V" ST-212-02V -75,2025 r180 top
CN12 "JTAG" 2*3P#1 2075,1075 r90 top
CN13 "USB-typeB connector" USB-B 3825,2125 r90 top
CN14 "DC-10B" DC10B -50,750 r0 top
CN15 "3.2\" LCD_connector (MB785 with AM-240320D4TOQW-T00H(R))" AM240*320AA 3575,2125 r270 top locked
D1 "BAT60JFILM" SOD-323 2600,5450 r180 top
D2 "BAT60JFILM" SOD-323 1348.28,4010 r90 top
D3 "BAT60JFILM" SOD-323 1350,3800 r270 top
D4 "LBZX84C5V6LT1G" SOT-23#1 2475,1700 r0 top
D5 "LBZX84C5V6LT1G" SOT-23#1 2825,1900 r0 top
D6 "LBZX84C5V6LT1G" SOT-23#1 2650,1900 r0 top
D7 "LBZX84C5V6LT1G" SOT-23#1 2475,1900 r0 top
D8 "LBZX84C5V6LT1G" SOT-23#1 2825,1700 r0 top
D9 "LBZX84C5V6LT1G" SOT-23#1 2650,1700 r0 top
JP1 "" SIP3 1050,5775 r0 top locked
JP2 "" SIP2 1625,5900 r270 top locked
JP3 "" SIP2 2975,5800 r90 top locked
JP4 "" SIP3 1475,5800 r90 top locked
JP5 "" SIP3 1025,5150 r90 top
JP6 "" SIP3 2600,4825 r90 top
JP7 "" SIP2 950,4350 r270 top
JP8 "" SIP2 1125,4350 r270 top
JP9 "" SIP2 1300,4250 r90 top
JP10 "" SIP2 1300,2975 r0 top locked
JP11 "" SIP2 2150,2825 r0 top locked
JP12 "" SIP2 3025,2575 r270 top locked
JP13 "" 2*3P#2 1050,2450 r90 top locked
JP14 "" SIP2 1725,2450 r90 top
JP15 "" SIP2 1450,2450 r90 top
L1 "BEAD" 0603L 2475,3350 r270 top
L2 "BEAD" 0603L 1425,1400 r180 top
L3 "BEAD" 0603L 1425,1100 r180 top
LD1 "Green" 0603D 2200,2450 r90 top
LD2 "Orange" 0603D 2075,2450 r90 top
LD3 "Red" 0603D 1950,2450 r90 top
LD4 "Blue" 0603D 1825,2450 r90 top
LD5 "HSMF-A201-A00J1" LED2-28*32 4025,1525 r0 top
LD6 "red" 0603D -50,1600 r0 top
mp1 "" MARKPOINT_1.0 3625,6075 r0 top
mp2 "" MARKPOINT_1.0 50,-80 r0 top
R1 "0" 0603R 250,5925 r0 top
R2 "100" 0603R 250,5850 r180 top
R3 "0" 0603R 2175,5825 r90 top
R4 "0" 0603R 2275,5825 r270 top
R5 "0" 0603R 2375,5825 r270 top
R6 "0" 0603R 2475,5825 r270 top
R7 "0" 0603R 2575,5825 r90 top
R8 "0" 0603R 2875,5825 r90 top
R9 "100K" 0603R 2575,5675 r270 top
R10 "3.3K" 0603R 2775,5825 r90 top
R11 "820" 0603R 3100,5450 r180 top
R12 "27K" 0603R 2600,5350 r0 top
R13 "10K" 0402R#1 2725,5450 r90 top
R14 "10K" 0402R#1 2800,5450 r90 top
R15 "10K" 0402R#1 475,5375 r180 top
R16 "0" 0603R 475,5300 r0 top
R17 "10K" 0402R#1 1550,5375 r180 top
R18 "0" 0603R 2400,5325 r270 top
R19 "33K" 0603R 2600,5250 r0 top
R20 "820" 0603R 3100,5350 r0 top
R21 "10K" 0402R#1 1325,5150 r0 top
R22 "0" 0603R 1325,5225 r0 top
R23 "10K" 0402R#1 2400,5175 r90 top
R24 "0" 0603R 475,5100 r180 top
R25 "10K" 0402R#1 1325,5100 r180 top
R26 "18K" 0603R 2600,5150 r180 top
R27 "10K" 0402R#1 1150,4975 r90 top
R28 "0" 0603R 1325,5025 r180 top
R29 "270K" 0603R 2700,5050 r270 top
R30 "10K" 0402R#1 2825,5050 r270 top
R31 "10K" 0402R#1 1100,4975 r90 top
R32 "10K" 0402R#1 1325,4950 r180 top
R33 "0" 0603R 1200,4975 r270 top
R34 "10K" 0402R#1 2775,5050 r270 top
R35 "0" 0603R 2925,4875 r90 top
R36 "0" 0603R 1325,4875 r0 top
R37 "0" 0603R 2695,4875 r90 top
R38 "0" 0603R 2770,4875 r90 top
R39 "0" 0603R 2850,4875 r90 top
R40 "10K" 0402R#1 1850,4625 r0 top
R41 "[N/A]" 0603R 375,4400 r270 top
R42 "50" 0603R 3675,4200 r180 top
R43 "0" 0603R 1225,4100 r270 top
R44 "0" 0603R 2775,4000 r90 top
R45 "10K" 0402R#1 2850,4000 r90 top
R46 "0" 0603R 2925,4000 r270 top
R47 "0" 0603R 2750,3800 r180 top
R48 "0" 0603R 2750,3700 r180 top
R49 "0" 0603R 2925,3700 r180 top
R50 "10K" 0402R#1 1225,3575 r270 top
R51 "0" 0603R 2925,3600 r180 top
R52 "10K" 0402R#1 2850,3500 r180 top
R53 "10K" 0402R#1 2975,3500 r180 top
R54 "[N/A]" 0603R 3750,3450 r0 top
R55 "22K" 0603R 975,3450 r270 top
R56 "22K" 0603R 1200,3450 r90 top
R57 "[N/A]" 0603R 3750,3350 r0 top
R58 "120" 0603R 1275,3275 r0 top
R59 "0" 0603R 1750,3350 r270 top
R60 "0" 0603R 1825,3350 r270 top
R61 "0" 0603R 2275,3350 r90 top
R62 "47" 0603R 2375,3350 r90 top
R63 "[N/A]" 0603R 3750,3250 r0 top
R64 "390" 0603R 2025,3225 r90 top
R65 "[N/A]" 0603R 3750,3150 r180 top
R66 "0" 0603R 1275,3125 r180 top
R67 "[N/A]" 0603R 3750,3050 r0 top
R68 "10K" 0402R#1 3750,2950 r180 top
R69 "[N/A]" 0603R 3750,2850 r0 top
R70 "10K" 0402R#1 3750,2750 r180 top
R71 "10K" 0402R#1 3750,2650 r180 top
R72 "0" 0603R 2400,2600 r0 top
R73 "680" 0603R 1825,2600 r270 top
R74 "680" 0603R 1950,2600 r270 top
R75 "680" 0603R 2075,2600 r270 top
R76 "330" 0603R 2200,2600 r270 top
R77 "0" 0603R 2400,2525 r0 top
R78 "0" 0603R 2400,2450 r180 top
R79 "10K" 0402R#1 2900,2525 r180 top
R80 "10K" 0402R#1 2400,2350 r0 top
R81 "100K" 0603R 2750,1025 r270 top
R82 "10K" 0402R#1 500,2150 r0 top
R83 "4K7" 0603R 950,2075 r90 top
R84 "10K" 0402R#1 3425,2050 r0 top
R85 "0" 0603R 3425,2125 r0 top
R86 "10K" 0402R#1 1850,2050 r90 top
R87 "100K" 0603R 3025,1700 r90 top
R88 "100K" 0603R 2725,1575 r0 top
R89 "100" 0603R 3825,1525 r90 top
R90 "100" 0603R 3900,1525 r270 top
R91 "4K7" 0603R 2950,1700 r270 top
R92 "1K" 0603R 125,1600 r180 top
R93 "4K7" 0603R 2950,1850 r270 top
R94 "10K" 0402R#1 1850,1525 r270 top
R95 "[N/A]" 0603R 3425,1125 r180 top
R96 "47" 0603R 3950,1050 r0 top
R97 "[N/A]" 0603R 3000,1025 r270 top
R98 "0" 0603R 3425,1025 r0 top
R99 "0" 0603R 3200,875 r90 top
R100 "10K" 0402R#1 3950,900 r0 top
R101 "330" 0603R 1750,850 r270 top
R102 "4K7" 0603R 1850,850 r270 top
R103 "0" 0603R 1950,850 r270 top
R104 "0" 0603R 2050,850 r270 top
R105 "0" 0603R 2125,850 r270 top
R106 "0" 0603R 2200,850 r270 top
R107 "0" 0603R 2275,850 r270 top
R108 "0" 0603R 2350,850 r270 top
R109 "0" 0603R 2450,850 r270 top
R110 "0" 0603R 3950,800 r180 top
R111 "[N/A]" 0603R 1625,850 r270 top
R112 "4K7" 0603R 2925,700 r180 top
R113 "10K" 0402R#1 3050,875 r270 top
R114 "10K" 0402R#1 3125,875 r270 top
R115 "5" 0603R 3950,725 r180 top
R116 "220K" 0603R 1850,650 r90 top
R117 "10K" 0402R#1 2050,650 r90 top
R118 "10K" 0402R#1 2125,650 r270 top
R119 "10K" 0402R#1 2200,650 r90 top
R120 "10K" 0402R#1 2275,650 r90 top
R121 "10K" 0402R#1 2350,650 r90 top
R122 "4K7" 0603R 2550,650 r90 top
R123 "10K" 0402R#1 2925,600 r0 top
R124 "100" 0603R 1750,475 r270 top
R125 "100" 0603R 1950,475 r270 top
R126 "100K" 0603R 3075,500 r180 top
R127 "100" 0603R 2450,475 r90 top
R128 "100" 0603R 2550,475 r270 top
R129 "10K" 0402R#2 2925,1025 r270 top
R130 "10K" 0402R#2 3700,2300 r270 top
R131 "0" 0603R 4150,1525 r270 top
R132 "36K" 0603R 3650,2300 r90 top
R133 "10" 0603R 3425,1725 r180 top
R134 "10" 0603R 3425,1800 r180 top
R135 "1.5K" 0603R 3425,1875 r180 top
R136 "0" 0603R 1425,1300 r180 top
R137 "[N/A]" 0603R 1425,1200 r180 top
R138 "0" 0603R 1050,4975 r270 top
RS1 "RS8M22R0J1" RES8B_0402 2750,2100 r0 top
RV1 "3386P-103H[10%]" 3296W 4000,325 r180 top
SB1 "" JP2_SMD 2875,5450 r90 top
SB2 "" JP2_SMD 3675,4125 r180 top
SB3 "" JP2_SMD 1050,3450 r270 top
SB4 "" JP2_SMD 1125,3450 r270 top
SB5 "" JP2_SMD 1600,3350 r90 top
SB6 "" JP2_SMD 1900,3350 r90 top
SB7 "" JP2_SMD 1275,3200 r180 top
SB8 "" JP2_SMD 2900,2450 r180 top
SB9 "" JP2_SMD 2975,875 r90 top
SB10 "" JP2_SMD 1775,1525 r90 top
T1 "9013" SOT-23#2 3550,2300 r90 top
TP1 "AIN+" TP 2900,3800 r0 top
TP2 "AIN-" TP 3000,3800 r0 top
TP3 "VREF" TP 2225,3200 r180 top
TP4 "5V" TP 1575,2600 r180 top
TP5 "3V3" TP 1575,2450 r0 top
TP6 "MCO" TP 2375,4750 r0 top
TP7 "Ground" TP 275,-25 r180 top
U1 "TSOP34836" TSOP34836 50,5800 r270 top
U2 "HDMI2C1-5DIJ" QFN16(5*4) 2800,5250 r90 top
U3 "IS61WV102416BLL-10MLI" FBGA48(9*11) 2150,5075 r0 top
U4 "KFG1216U2B-DIB6" FBGA63(9.5*12) 1625,5075 r0 top
U5 "ST3232ECTR" TSSOP16 950,4600 r90 top
U6 "M25P128-VME6G" VDFPN8(8*6) 2875,4275 r90 top
U7 "ST3241EBPR" SSOP28 1100,3825 r90 top
U8 "STM32F100ZET6" IC149-144-045-B5 2025,4000 r0 top
U9 "ST485ABDR" SO8 975,3075 r0 top
U10 "STLM75M2E" SO8 2550,2600 r270 top
U11 "TS4956EIJT" "18-BUMP FLIP-CHIP" 800,1875 r90 top
U12 "KDMG15008-03" KS1508 1375,1925 r90 top
U13 "M24C64-WMN6TP" SO8 1775,1675 r0 top
U14 "STM32F103C8T6" LQFP48 2750,1325 r90 top
U15 "BNX002-01" BNX001 50,1275 r90 top
U16 "TFDU6300" IR_VISHAY3 4075,825 r0 top
U17 "LD1086D2M33TR" D2PAK/A 1125,800 r90 top
U18 "ZEN056V130A24LS" polyzen 700,625 r90 top
U19 "STMPE811QTR" QFN16(3X3) 3100,650 r180 top
U20 "MT008-A" JOY 2700,-160 r45 top
X1 "8MHz (with socket)" XTAL_socket 2025,3050 r0 top
X2 "MC306-G-06Q-32.768 (manufacturer JFVNY)" SM8 1625,3075 r270 top
X3 "8MHz" SMT_XTAL 3200,1250 r270 top
Z1 "SMAJ5.0A-TR" 1R1C 700,950 r270 top

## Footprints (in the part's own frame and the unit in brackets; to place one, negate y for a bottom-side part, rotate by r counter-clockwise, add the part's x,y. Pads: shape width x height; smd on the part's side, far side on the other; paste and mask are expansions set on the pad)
1R1C [mm]
  rect 1.75x2.3 smd: 1(0,-1.9) 2(0,1.9)
  silkscreen extent -1.5,-2.2 1.5,2.2
2*3P#1 [mil]
  round 60 hole 40: 1(0,0) 2(100,0) 3(0,-100) 4(100,-100) 5(0,-200)
  silkscreen extent -50,-250 150,50
2*3P#2 [mil]
  round 60 hole 40: 1(0,0) 2(100,0) 3(0,-100) 4(100,-100) 5(0,-200) 6(100,-200)
  silkscreen extent -50,-250 150,50
2*35P [mil]
  round 60 hole 40: 1(0,0) 2(100,0) 3(0,-100) 4(100,-100) 5(0,-200) 6(100,-200) 7(0,-300) 8(100,-300) 9(0,-400) 10(100,-400) 11(0,-500) 12(100,-500) 13(0,-600) 14(100,-600) 15(0,-700) 16(100,-700) 17(0,-800) 18(100,-800) 19(0,-900) 20(100,-900) 21(0,-1000) 22(100,-1000) 23(0,-1100) 24(100,-1100) 25(0,-1200) 26(100,-1200) 27(0,-1300) 28(100,-1300) 29(0,-1400) 30(100,-1400) 31(0,-1500) 32(100,-1500) 33(0,-1600) 34(100,-1600) 35(0,-1700) 36(100,-1700) 37(0,-1800) 38(100,-1800) 39(0,-1900) 40(100,-1900) 41(0,-2000) 42(100,-2000) 43(0,-2100) 44(100,-2100) 45(0,-2200) 46(100,-2200) 47(0,-2300) 48(100,-2300) 49(0,-2400) 50(100,-2400) 51(0,-2500) 52(100,-2500) 53(0,-2600) 54(100,-2600) 55(0,-2700) 56(100,-2700) 57(0,-2800) 58(100,-2800) 59(0,-2900) 60(100,-2900) 61(0,-3000) 62(100,-3000) 63(0,-3100) 64(100,-3100) 65(0,-3200) 66(100,-3200) 67(0,-3300) 68(100,-3300) 69(0,-3400) 70(100,-3400)
  silkscreen extent -50,-3450 150,50
"18-BUMP FLIP-CHIP" [mil]
  round 8.5 smd: A1(-34.09,-29.53) A3(-34.09,-9.84) A5(-34.09,9.84) A7(-34.09,29.53) B2(-17.05,-19.68) B4(-17.05,0) B6(-17.05,19.68) C1(0,-29.53) C3(0,-9.84) C5(0,9.84) C7(0,29.53) D2(17.05,-19.68) D4(17.05,0) D6(17.05,19.68) E1(34.09,-29.53) E3(34.09,-9.84) E5(34.09,9.84) E7(34.09,29.53)
  TopLayer lines w5: -39.37,49.21 -47.24,49.21 -47.24,39.37 ; 39.37,49.21 47.24,49.21 47.24,39.37 ; -47.24,-39.37 -47.24,-49.21 -39.37,-49.21 ; 47.24,-39.37 47.24,-49.21 39.37,-49.21
  silkscreen extent -67,-63 -59,-55
0402C#1 [mil]
  rect 15x20 smd: 1(19.5,0) 2(-19.5,0)
  silkscreen extent -31,-14 32,14
0402C#2 [mil]
  rect 18x20 smd: 1(19,0) 2(-19,0)
  silkscreen extent -31,-14 31,14
0402R#1 [mil]
  rect 15x20 smd: 1(19.5,0) 2(-19.5,0)
  silkscreen extent -30,-14 32,14
0402R#2 [mil]
  rect 18x20 smd: 1(19,0) 2(-19,0)
  silkscreen extent -31,-14 31,14
0603C [mil]
  rect 30x30 smd: 1(27.5,0) 2(-27.5,0)
  silkscreen extent -50,-20 50,20
0603D [mil]
  rect 30x30 smd: 1(27.5,0) 2(-27.5,0)
  silkscreen extent -50,-25 55,25
0603L [mil]
  rect 30x30 smd: 1(27.5,0) 2(-27.5,0)
  silkscreen extent -50,-20 50,20
0603R [mil]
  rect 30x30 smd: 1(27.5,0) 2(-27.5,0)
  silkscreen extent -50,-20 50,20
1206C [mil]
  rect 50x60 smd: 1(60,0) 2(-60,0)
  silkscreen extent -95,-40 95,40
3296W [mil]
  round 50 hole 28: 1(-100,0) 2(0,100) 3(100,0)
  silkscreen extent -190,-190 190,190
0471510101 [mm]
  round 0.9 hole 0.9: 0(-7.25,-7.137) 0(-7.25,-6.909) 0(-7.25,-6.502) 0(-7.25,-6.299) 0(-7.25,-1.674) 0(-7.25,-1.446) 0(-7.25,-1.141) 0(-7.25,-0.379) 0(-7.25,-0.1) 0(-7.25,0.205) 0(7.25,-7.137) 0(7.25,-6.909) 0(7.25,-6.502) 0(7.25,-6.299) 0(7.264,-1.676) 0(7.264,-1.448) 0(7.264,-1.143) 0(7.264,-0.381) 0(7.264,-0.102) 0(7.264,0.203)
  oval 1.5x2.3 hole 0.9: 0(-7.25,-6.72) 0(7.25,-6.72)
  oval 1.5x3.3 hole 0.9: 0(-7.25,-0.76) 0(7.264,-0.762)
  rect 0.3x2.6 smd: 1(4.5,0) 2(4,0) 3(3.5,0) 4(3,0) 5(2.5,0) 6(2,0) 7(1.5,0) 8(1,0) 9(0.5,0) 10(0,0) 11(-0.5,0) 12(-1,0) 13(-1.5,0) 14(-2,0) 15(-2.5,0) 16(-3,0) 17(-3.5,0) 18(-4,0) 19(-4.5,0)
  silkscreen extent -7.5,-10.1 7.5,1.3
AM240*320AA [mil]
  round 125.98 hole 125.98 unplated: 0(446,-3211.94) 0(1863.72,-3211.94)
  round 60 hole 40: 1(0,0) 2(0,100) 3(100,0) 4(100,100) 5(200,0) 6(200,100) 7(300,0) 8(300,100) 9(400,0) 10(400,100) 11(500,0) 12(500,100) 13(600,0) 14(600,100) 15(700,0) 16(700,100) 17(800,0) 18(800,100) 19(900,0) 20(900,100) 21(1000,0) 22(1000,100) 23(1100,0) 24(1100,100) 25(1200,0) 26(1200,100) 27(1300,0) 28(1300,100) 29(1400,0) 30(1400,100) 31(1500,0) 32(1500,100) 33(1600,0) 34(1600,100)
  silkscreen extent -170,-3310 2020,200
BNX001 [mm]
  round 1.8 hole 1.4: 1(2.5,2.5) 2(-2.5,2.5) 3(2.5,-2.5) 4(0,0) 5(5,0) 6(-2.5,-2.5)
  silkscreen extent -5,-5 5.76,5
C160M [mil]
  rect 100x80 smd paste-19.68 mask+4: 1(85,0) 2(-85,0)
  silkscreen extent -83,-83 83,83
C310M [mil]
  rect 200x120 smd paste-23.62 mask-23.62: 1(125,0) 2(-125,0)
  silkscreen extent -163,-163 163,163
D2PAK/A [mm]
  rect 2.8x1 smd: 1(11.4,-2.54) 2(11.4,0)
  rect 8x10.2 smd: 2(0,0)
  rect 2.8x1.42 smd: 3(11.4,2.54)
  silkscreen extent -4.06,-5.08 6.35,5.08
DB9/M [mil]
  round 50 hole 50: 0(-538,55) 0(-523,55) 0(-508,55) 0(-493,55) 0(-478,55) 0(-463,55) 0(-448,55) 0(448,55) 0(463,55) 0(478,55) 0(493,55) 0(508,55) 0(523,55) 0(538,55)
  oval 170x80 hole 50: 0(-493,55) 0(493,55)
  rect 70x80 hole 38: 1(218,0)
  oval 70x80 hole 38: 2(109,0) 3(0,0) 4(-109,0) 5(-218,0) 6(164,110) 7(55,110) 8(-54,110) 9(-163,110)
  silkscreen extent -618,-100 618,410
DC10B [mil]
  round 45 hole 30: 1(244.09,-40) 1(244.09,-20) 1(244.09,20) 1(244.09,40) 2(82.05,-196.85) 2(102.05,-196.85) 2(142.05,-196.85) 2(162.05,-196.85) 3(0,-40) 3(0,-20) 3(0,20) 3(0,40)
  oval 80x180 hole 30: 1(244.1,0) 3(0,0)
  oval 180x80 hole 30: 2(122.05,-196.85)
  silkscreen extent -175,-170 290,180
FBGA48(9*11) [mil]
  round 12 smd: A1(-73.82,103.35) A2(-44.29,103.35) A3(-14.76,103.35) A4(14.76,103.35) A5(44.29,103.35) A6(73.82,103.35) B1(-73.82,73.82) B2(-44.29,73.82) B3(-14.76,73.82) B4(14.76,73.82) B5(44.29,73.82) B6(73.82,73.82) C1(-73.82,44.29) C2(-44.29,44.29) C3(-14.76,44.29) C4(14.76,44.29) C5(44.29,44.29) C6(73.82,44.29) D1(-73.82,14.76) D2(-44.29,14.76) D3(-14.76,14.76) D4(14.76,14.76) D5(44.29,14.76) D6(73.82,14.76) E1(-73.82,-14.76) E2(-44.29,-14.76) E3(-14.76,-14.76) E4(14.76,-14.76) E5(44.29,-14.76) E6(73.82,-14.76) F1(-73.82,-44.29) F2(-44.29,-44.29) F3(-14.76,-44.29) F4(14.76,-44.29) F5(44.29,-44.29) F6(73.82,-44.29) G1(-73.82,-73.82) G2(-44.29,-73.82) G3(-14.76,-73.82) G4(14.76,-73.82) G5(44.29,-73.82) G6(73.82,-73.82) H1(-73.82,-103.35) H2(-44.29,-103.35) H3(-14.76,-103.35) H4(14.76,-103.35) H5(44.29,-103.35) H6(73.82,-103.35)
  TopLayer lines w5: -177.17,-196.85 -177.17,-216.54 -157.48,-216.54 ; -177.17,196.85 -177.17,216.54 -157.48,216.54 ; 157.48,-216.54 177.17,-216.54 177.17,-196.85 ; 157.48,216.54 177.17,216.54 177.17,196.85
  silkscreen extent -158,167 -138,187
FBGA63(9.5*12) [mm]
  round 0.25 smd: A1(-2,2.8) A2(-1.2,2.8) A3(-0.4,2.8) A4(0.4,2.8) A5(1.2,2.8) A6(2,2.8) B1(-2,2) B2(-1.2,2) B3(-0.4,2) B4(0.4,2) B5(1.2,2) B6(2,2) C1(-2,1.2) C2(-1.2,1.2) C3(-0.4,1.2) C4(0.4,1.2) C5(1.2,1.2) C6(2,1.2) D1(-2,0.4) D2(-1.2,0.4) D3(-0.4,0.4) D4(0.4,0.4) D5(1.2,0.4) D6(2,0.4) E1(-2,-0.4) E2(-1.2,-0.4) E3(-0.4,-0.4) E4(0.4,-0.4) E5(1.2,-0.4) E6(2,-0.4) F1(-2,-1.2) F2(-1.2,-1.2) F3(-0.4,-1.2) F4(0.4,-1.2) F5(1.2,-1.2) F6(2,-1.2) G1(-2,-2) G2(-1.2,-2) G3(-0.4,-2) G4(0.4,-2) G5(1.2,-2) G6(2,-2) H1(-2,-2.8) H2(-1.2,-2.8) H3(-0.4,-2.8) H4(0.4,-2.8) H5(1.2,-2.8) H6(2,-2.8) J0(-3.6,-4.4) J0(-3.6,-3.6) J0(-3.6,3.6) J0(-3.6,4.4) J0(-2.8,-4.4) J0(-2.8,-3.6) J0(-2.8,4.4) J0(2.8,3.6) J0(2.8,-4.4) J0(2.8,-3.6) J0(2.8,4.4) J0(3.6,-4.4) J0(3.6,-3.6) J0(3.6,3.6) J0(3.6,4.4)
  TopLayer lines w0.127: -4.75,-5.5 -4.75,-6 -4.25,-6 ; -4.75,5.5 -4.75,6 -4.25,6 ; 4.25,-6 4.75,-6 4.75,-5.5 ; 4.25,6 4.75,6 4.75,5.5
  silkscreen extent -5.5,6.25 -5,6.75
IC149-144-045-B5 [mm]
  rect 1x2.5 smd rot 45: 0(-11,-11) 0(11,11)
  rect 1x2.5 smd rot 135: 0(-11,11) 0(11,-11)
  round 1.5 hole 1.5 unplated: 0(0,-8) 0(0,8)
  rect 0.22x1.6 smd: 1(-8.75,-10.9) 2(-8.25,-10.9) 3(-7.75,-10.9) 4(-7.25,-10.9) 5(-6.75,-10.9) 6(-6.25,-10.9) 7(-5.75,-10.9) 8(-5.25,-10.9) 9(-4.75,-10.9) 10(-4.25,-10.9) 11(-3.75,-10.9) 12(-3.25,-10.9) 13(-2.75,-10.9) 14(-2.25,-10.9) 15(-1.75,-10.9) 16(-1.25,-10.9) 17(-0.75,-10.9) 18(-0.25,-10.9) 19(0.25,-10.9) 20(0.75,-10.9) 21(1.25,-10.9) 22(1.75,-10.9) 23(2.25,-10.9) 24(2.75,-10.9) 25(3.25,-10.9) 26(3.75,-10.9) 27(4.25,-10.9) 28(4.75,-10.9) 29(5.25,-10.9) 30(5.75,-10.9) 31(6.25,-10.9) 32(6.75,-10.9) 33(7.25,-10.9) 34(7.75,-10.9) 35(8.25,-10.9) 36(8.75,-10.9) 73(8.75,10.9) 74(8.25,10.9) 75(7.75,10.9) 76(7.25,10.9) 77(6.75,10.9) 78(6.25,10.9) 79(5.75,10.9) 80(5.25,10.9) 81(4.75,10.9) 82(4.25,10.9) 83(3.75,10.9) 84(3.25,10.9) 85(2.75,10.9) 86(2.25,10.9) 87(1.75,10.9) 88(1.25,10.9) 89(0.75,10.9) 90(0.25,10.9) 91(-0.25,10.9) 92(-0.75,10.9) 93(-1.25,10.9) 94(-1.75,10.9) 95(-2.25,10.9) 96(-2.75,10.9) 97(-3.25,10.9) 98(-3.75,10.9) 99(-4.25,10.9) 100(-4.75,10.9) 101(-5.25,10.9) 102(-5.75,10.9) 103(-6.25,10.9) 104(-6.75,10.9) 105(-7.25,10.9) 106(-7.75,10.9) 107(-8.25,10.9) 108(-8.75,10.9)
  rect 1.6x0.22 smd: 37(10.9,-8.75) 38(10.9,-8.25) 39(10.9,-7.75) 40(10.9,-7.25) 41(10.9,-6.75) 42(10.9,-6.25) 43(10.9,-5.75) 44(10.9,-5.25) 45(10.9,-4.75) 46(10.9,-4.25) 47(10.9,-3.75) 48(10.9,-3.25) 49(10.9,-2.75) 50(10.9,-2.25) 51(10.9,-1.75) 52(10.9,-1.25) 53(10.9,-0.75) 54(10.9,-0.25) 55(10.9,0.25) 56(10.9,0.75) 57(10.9,1.25) 58(10.9,1.75) 59(10.9,2.25) 60(10.9,2.75) 61(10.9,3.25) 62(10.9,3.75) 63(10.9,4.25) 64(10.9,4.75) 65(10.9,5.25) 66(10.9,5.75) 67(10.9,6.25) 68(10.9,6.75) 69(10.9,7.25) 70(10.9,7.75) 71(10.9,8.25) 72(10.9,8.75) 109(-10.9,8.75) 110(-10.9,8.25) 111(-10.9,7.75) 112(-10.9,7.25) 113(-10.9,6.75) 114(-10.9,6.25) 115(-10.9,5.75) 116(-10.9,5.25) 117(-10.9,4.75) 118(-10.9,4.25) 119(-10.9,3.75) 120(-10.9,3.25) 121(-10.9,2.75) 122(-10.9,2.25) 123(-10.9,1.75) 124(-10.9,1.25) 125(-10.9,0.75) 126(-10.9,0.25) 127(-10.9,-0.25) 128(-10.9,-0.75) 129(-10.9,-1.25) 130(-10.9,-1.75) 131(-10.9,-2.25) 132(-10.9,-2.75) 133(-10.9,-3.25) 134(-10.9,-3.75) 135(-10.9,-4.25) 136(-10.9,-4.75) 137(-10.9,-5.25) 138(-10.9,-5.75) 139(-10.9,-6.25) 140(-10.9,-6.75) 141(-10.9,-7.25) 142(-10.9,-7.75) 143(-10.9,-8.25) 144(-10.9,-8.75)
  silkscreen extent -10.29,-10.29 10.29,10.29
IDC20S [mil]
  round 60 hole 40: 1(0,0) 2(100,0) 3(0,-100) 4(100,-100) 5(0,-200) 6(100,-200) 7(0,-300) 8(100,-300) 9(0,-400) 10(100,-400) 11(0,-500) 12(100,-500) 13(0,-600) 14(100,-600) 15(0,-700) 16(100,-700) 17(0,-800) 18(100,-800) 19(0,-900) 20(100,-900)
  silkscreen extent -125,-1100 250,200
IDC34S [mil]
  round 60 hole 40: 1(0,0) 2(100,0) 3(0,-100) 4(100,-100) 5(0,-200) 6(100,-200) 7(0,-300) 8(100,-300) 9(0,-400) 10(100,-400) 11(0,-500) 12(100,-500) 13(0,-600) 14(100,-600) 15(0,-700) 16(100,-700) 17(0,-800) 18(100,-800) 19(0,-900) 20(100,-900) 21(0,-1000) 22(100,-1000) 23(0,-1100) 24(100,-1100) 25(0,-1200) 26(100,-1200) 27(0,-1300) 28(100,-1300) 29(0,-1400) 30(100,-1400) 31(0,-1500) 32(100,-1500) 33(0,-1600) 34(100,-1600)
  silkscreen extent -125,-1800 250,200
IR_VISHAY3 [mm]
  rect 2x0.5 smd: 1(0,0) 2(0,0.95) 3(0,1.9) 4(0,2.85) 5(0,3.8) 6(0,4.75) 7(0,5.7) 8(0,6.65)
  silkscreen extent -1.1,-1 4.17,7.5
JOY [mm]
  round 1 hole 1 unplated: 0(0,-1.9)
  round 0.7 hole 0.7 unplated: 0(0,1.9)
  rect 1.778x1.016 smd: 1(-3.1,1.4) 2(-3.1,0) 3(-3.1,-1.4) 4(3.1,-1.4) 5(3.1,0) 6(3.1,1.4)
  silkscreen extent -3.8,-3.7 3.8,4.1
JP2_SMD [mil]
  oct 15x30 smd rot 45: 1(-18,-8) 2(18,7)
  oct 15.75x30 smd rot 135: 1(-18,8)
  rect 26x26 smd rot 45: 2(13,0)
  oct 15x30 smd rot 135: 2(18,-7)
KS1508 [mil]
  round 60 hole 40: 1(-149.61,0) 2(149.61,0)
  silkscreen extent -295,-295 295,295
LED2-28*32 [mm]
  rect 1.1x1.5 smd: 1(-0.75,-1.5) 2(-0.75,1.5) 3(0.75,1.5) 4(0.75,-1.5)
  silkscreen extent -1.27,-0.64 1.27,0.64
LI1220_1 [mm]
  round 1.1 hole 1.1 unplated: 0(-3.75,0)
  round 1.5 hole 1.5 unplated: 0(3.75,0.025)
  oct 4x2.5 smd: 1(8.255,0) 2(-8.128,0)
  silkscreen extent -7.57,-7.62 7.57,7.62
LQFP48 [mm]
  rect 0.2x1 smd: 1(-2.75,-4.25) 2(-2.25,-4.25) 3(-1.75,-4.25) 4(-1.25,-4.25) 5(-0.75,-4.25) 6(-0.25,-4.25) 7(0.25,-4.25) 8(0.75,-4.25) 9(1.25,-4.25) 10(1.75,-4.25) 11(2.25,-4.25) 12(2.75,-4.25) 25(2.75,4.25) 26(2.25,4.25) 27(1.75,4.25) 28(1.25,4.25) 29(0.75,4.25) 30(0.25,4.25) 31(-0.25,4.25) 32(-0.75,4.25) 33(-1.25,4.25) 34(-1.75,4.25) 35(-2.25,4.25) 36(-2.75,4.25)
  rect 1x0.2 smd: 13(4.25,-2.75) 14(4.25,-2.25) 15(4.25,-1.75) 16(4.25,-1.25) 17(4.25,-0.75) 18(4.25,-0.25) 19(4.25,0.25) 20(4.25,0.75) 21(4.25,1.25) 22(4.25,1.75) 23(4.25,2.25) 24(4.25,2.75) 37(-4.25,2.75) 38(-4.25,2.25) 39(-4.25,1.75) 40(-4.25,1.25) 41(-4.25,0.75) 42(-4.25,0.25) 43(-4.25,-0.25) 44(-4.25,-0.75) 45(-4.25,-1.25) 46(-4.25,-1.75) 47(-4.25,-2.25) 48(-4.25,-2.75)
  silkscreen extent -3.81,-3.81 3.81,3.81
MARKPOINT_1.0 [mil]
  round 40 smd: 0(0,0)
MSD(PJS008) [mm]
  round 0.7 hole 0.7 unplated: 0(0,0) 0(7.55,0)
  rect 0.8x1.6 smd: 1(1.475,5.8) 2(2.575,5.8) 3(3.675,5.8) 4(4.775,5.8) 5(5.875,5.8) 6(6.975,5.8) 7(8.075,5.8) 8(9.175,5.8)
  rect 0.85x1.6 smd: 9(10.325,5.8)
  rect 1.95x1.4 smd: 10(11.225,-4.4)
  rect 1.6x3.5 smd: G1(-3.4,3.65)
  rect 1.5x3.1 smd: G2(11.45,-7.35)
  rect 1.4x3.429 smd: G3(-3.5,-7.35)
  rect 1.2x3.1 smd: G4(11.6,4.15)
  silkscreen extent -3.81,-9.28 11.43,5.07
PB10 [mil]
  rect 40x60 smd: 1(-87.5,177.17) 2(87.5,177.17) 3(87.5,-177.17) 4(-87.5,-177.17)
  silkscreen extent -125,-125 125,125
polyzen [mm]
  rect 0.8x2.21 smd: 1(0,0)
  rect 0.7x0.94 smd: 2(3.429,0.635) 3(3.429,-0.635)
  silkscreen extent -0.38,-2.03 3.68,2.03
QFN16(3X3) [mil]
  rect 47.24x47.24 smd: 0(0,0)
  rect 10x28 smd: 1(-29.53,-58.74) 2(-9.84,-58.74) 3(9.84,-58.74) 4(29.53,-58.74) 9(29.53,58.74) 10(9.84,58.74) 11(-9.84,58.74) 12(-29.53,58.74)
  rect 28x10 smd: 5(58.74,-29.53) 6(58.74,-9.84) 7(58.74,9.84) 8(58.74,29.53) 13(-58.74,29.53) 14(-58.74,9.84) 15(-58.74,-9.84) 16(-58.74,-29.53)
  silkscreen extent -68,-68 59,59
QFN16(5*4) [mm]
  rect 0.6x0.25 smd: 1(-1.9,1.75) 2(-1.9,1.25) 3(-1.9,0.75) 4(-1.9,0.25) 5(-1.9,-0.25) 6(-1.9,-0.75) 7(-1.9,-1.25) 8(-1.9,-1.75) 9(1.9,-1.75) 10(1.9,-1.25) 11(1.9,-0.75) 12(1.9,-0.25) 13(1.9,0.25) 14(1.9,0.75) 15(1.9,1.25) 16(1.9,1.75)
  rect 2.45x4.35 smd: 5(0,0)
  silkscreen extent -2.92,-2.5 2,2.5
RES8B_0402 [mm]
  rect 0.25x0.5 smd: 1(-1.75,-0.584) 2(-1.75,0.584) 3(-1.25,-0.584) 4(-1.25,0.584) 5(-0.75,-0.584) 6(-0.75,0.584) 7(-0.25,-0.584) 8(-0.25,0.584) 9(0.25,-0.584) 10(0.25,0.584) 11(0.75,-0.584) 12(0.75,0.584) 13(1.25,-0.584) 14(1.25,0.584) 15(1.75,-0.584) 16(1.75,0.584)
  silkscreen extent -2.1,-0.5 2.1,0.5
SIP2 [mil]
  round 60 hole 40: 1(0,0) 2(100,0)
  silkscreen extent -50,-50 150,50
SIP3 [mil]
  rect 60x60 hole 40: 1(0,0)
  round 60 hole 40: 2(100,0) 3(200,0)
  silkscreen extent -50,-50 50,50
SM8 [mm]
  rect 1.9x1.3 smd: 1(-2.75,-1.6) 2(2.75,-1.6) 3(2.75,1.6) 4(-2.75,1.6)
  silkscreen extent -4.44,-1.91 4.44,1.91
SMT_XTAL [mil]
  rect 150x50 smd paste-11.81 mask-11.81: 1(-195,0) 2(195,0)
  silkscreen extent -214,-89 214,89
SO8 [mil]
  rect 24x76 smd: 1(0,0) 2(50,0) 3(100,0) 4(150,0) 5(150,225) 6(100,225) 7(50,225) 8(0,225)
  silkscreen extent -30,60 180,160
SOD-323 [mm]
  rect 0.6x0.45 smd: 1(1.143,0) 2(-1.143,0)
  silkscreen extent -0.67,-0.57 0.67,0.57
SOT-23#1 [mil]
  rect 36x36 smd: 1(37.5,-40) 2(-37.5,-40)
  rect 36x50 smd: 3(0.5,40)
  silkscreen extent -58,-45 58,45
SOT-23#2 [mil]
  rect 36x36 smd: 1(40,37.5) 2(40,-37.5)
  rect 50x36 smd: 3(-40,0.5)
  silkscreen extent -45,-58 45,58
SSOP28 [mm]
  rect 0.95x0.3 smd: 1(-3.8,4.225) 2(-3.8,3.575) 3(-3.8,2.925) 4(-3.8,2.275) 5(-3.8,1.625) 6(-3.8,0.975) 7(-3.8,0.325) 8(-3.8,-0.325) 9(-3.8,-0.975) 10(-3.8,-1.625) 11(-3.8,-2.275) 12(-3.8,-2.925) 13(-3.8,-3.575) 14(-3.8,-4.225) 15(3.8,-4.225) 16(3.8,-3.575) 17(3.8,-2.925) 18(3.8,-2.275) 19(3.8,-1.625) 20(3.8,-0.975) 21(3.8,-0.325) 22(3.8,0.325) 23(3.8,0.975) 24(3.8,1.625) 25(3.8,2.275) 26(3.8,2.925) 27(3.8,3.575) 28(3.8,4.225)
  silkscreen extent -2.56,-4.55 2.56,4.55
ST-212-02V [mil]
  round 45 hole 45 unplated: 0(-393.7,-196.85) 0(-393.7,196.85) 0(-196.85,0) 0(0,196.85) 0(0,-196.85) 0(98.43,196.85) 0(98.43,-196.85)
  round 60 hole 40: 1(0,0) 2(-196.85,196.85) 3(-196.85,-196.85) 4(-393.7,98.43) 5(-393.7,0) 6(-393.7,-98.43)
  silkscreen extent -480,-248 268,248
TAN-A#1 [mil]
  rect 50x60 smd: 1(-55,0) 2(55,0)
  silkscreen extent -105,-45 95,45
TAN-A#2 [mil]
  rect 50x60 smd: 1(55,0) 2(-55,0)
  silkscreen extent -95,-45 105,45
TP [mil]
  round 60 hole 40: 1(0,0)
  silkscreen extent -45,-45 45,45
TSOP34836 [mil]
  oval 40x60 hole 30: 1(-100,0) 2(0,0) 3(100,0)
  silkscreen extent -118,-209 118,51
TSSOP16 [mm]
  rect 1.15x0.3 smd: 1(0,0) 2(0,-0.65) 3(0,-1.3) 4(0,-1.95) 5(0,-2.6) 6(0,-3.25) 7(0,-3.9) 8(0,-4.55) 9(6.4,-4.55) 10(6.4,-3.9) 11(6.4,-3.25) 12(6.4,-2.6) 13(6.4,-1.95) 14(6.4,-1.3) 15(6.4,-0.65) 16(6.4,0)
  silkscreen extent 0.94,-4.88 5.42,0.33
USB-B [mil]
  round 120 hole 95: 0(-291,-185) 0(189,-185)
  round 50 hole 30: 1(0,0) 2(-98,0) 3(-98,-80) 4(0,-80)
  silkscreen extent -365,-591 263,57
VB334 [mm]
  round 2 hole 1.3: 1(-3.125,3.125) 2(3.125,3.125) 3(3.125,-3.125) 4(-3.125,-3.125)
  round 2.032 hole 1.27: 5(0,0)
  silkscreen extent -5.5,-5.5 5.5,5.5
VDFPN8(8*6) [mm]
  rect 2.54x4.064 smd: 0(0,0)
  rect 1x0.5 smd: 1(-3.81,1.905) 2(-3.81,0.635) 3(-3.81,-0.635) 4(-3.81,-1.905) 5(3.81,-1.905) 6(3.81,-0.635) 7(3.81,0.635) 8(3.81,1.905)
  silkscreen extent -4,-3.04 4,3.01
XTAL_socket [mil]
  round 80 hole 53: 1(100,0) 2(-100,0)
  silkscreen extent -215,-89 214,89

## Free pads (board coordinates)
  round 137.8 hole 137.8 unplated: 0(0,-200) 0(0,6150) 0(4050,-200) 0(4050,6150)
  round 20 smd: 0(1420,5430) 0(1500,3475) 0(1900,4775) 0(2450,5305) 0(2550,4475)

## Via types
v1: diameter 16, hole 8, TopLayer to BottomLayer, tented both sides, 671 vias
v2: diameter 16, hole 8, TopLayer to BottomLayer, 117 vias
v3: diameter 50, hole 28, TopLayer to BottomLayer, 5 vias
v4: diameter 50, hole 28, TopLayer to BottomLayer, tented both sides, 1 vias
